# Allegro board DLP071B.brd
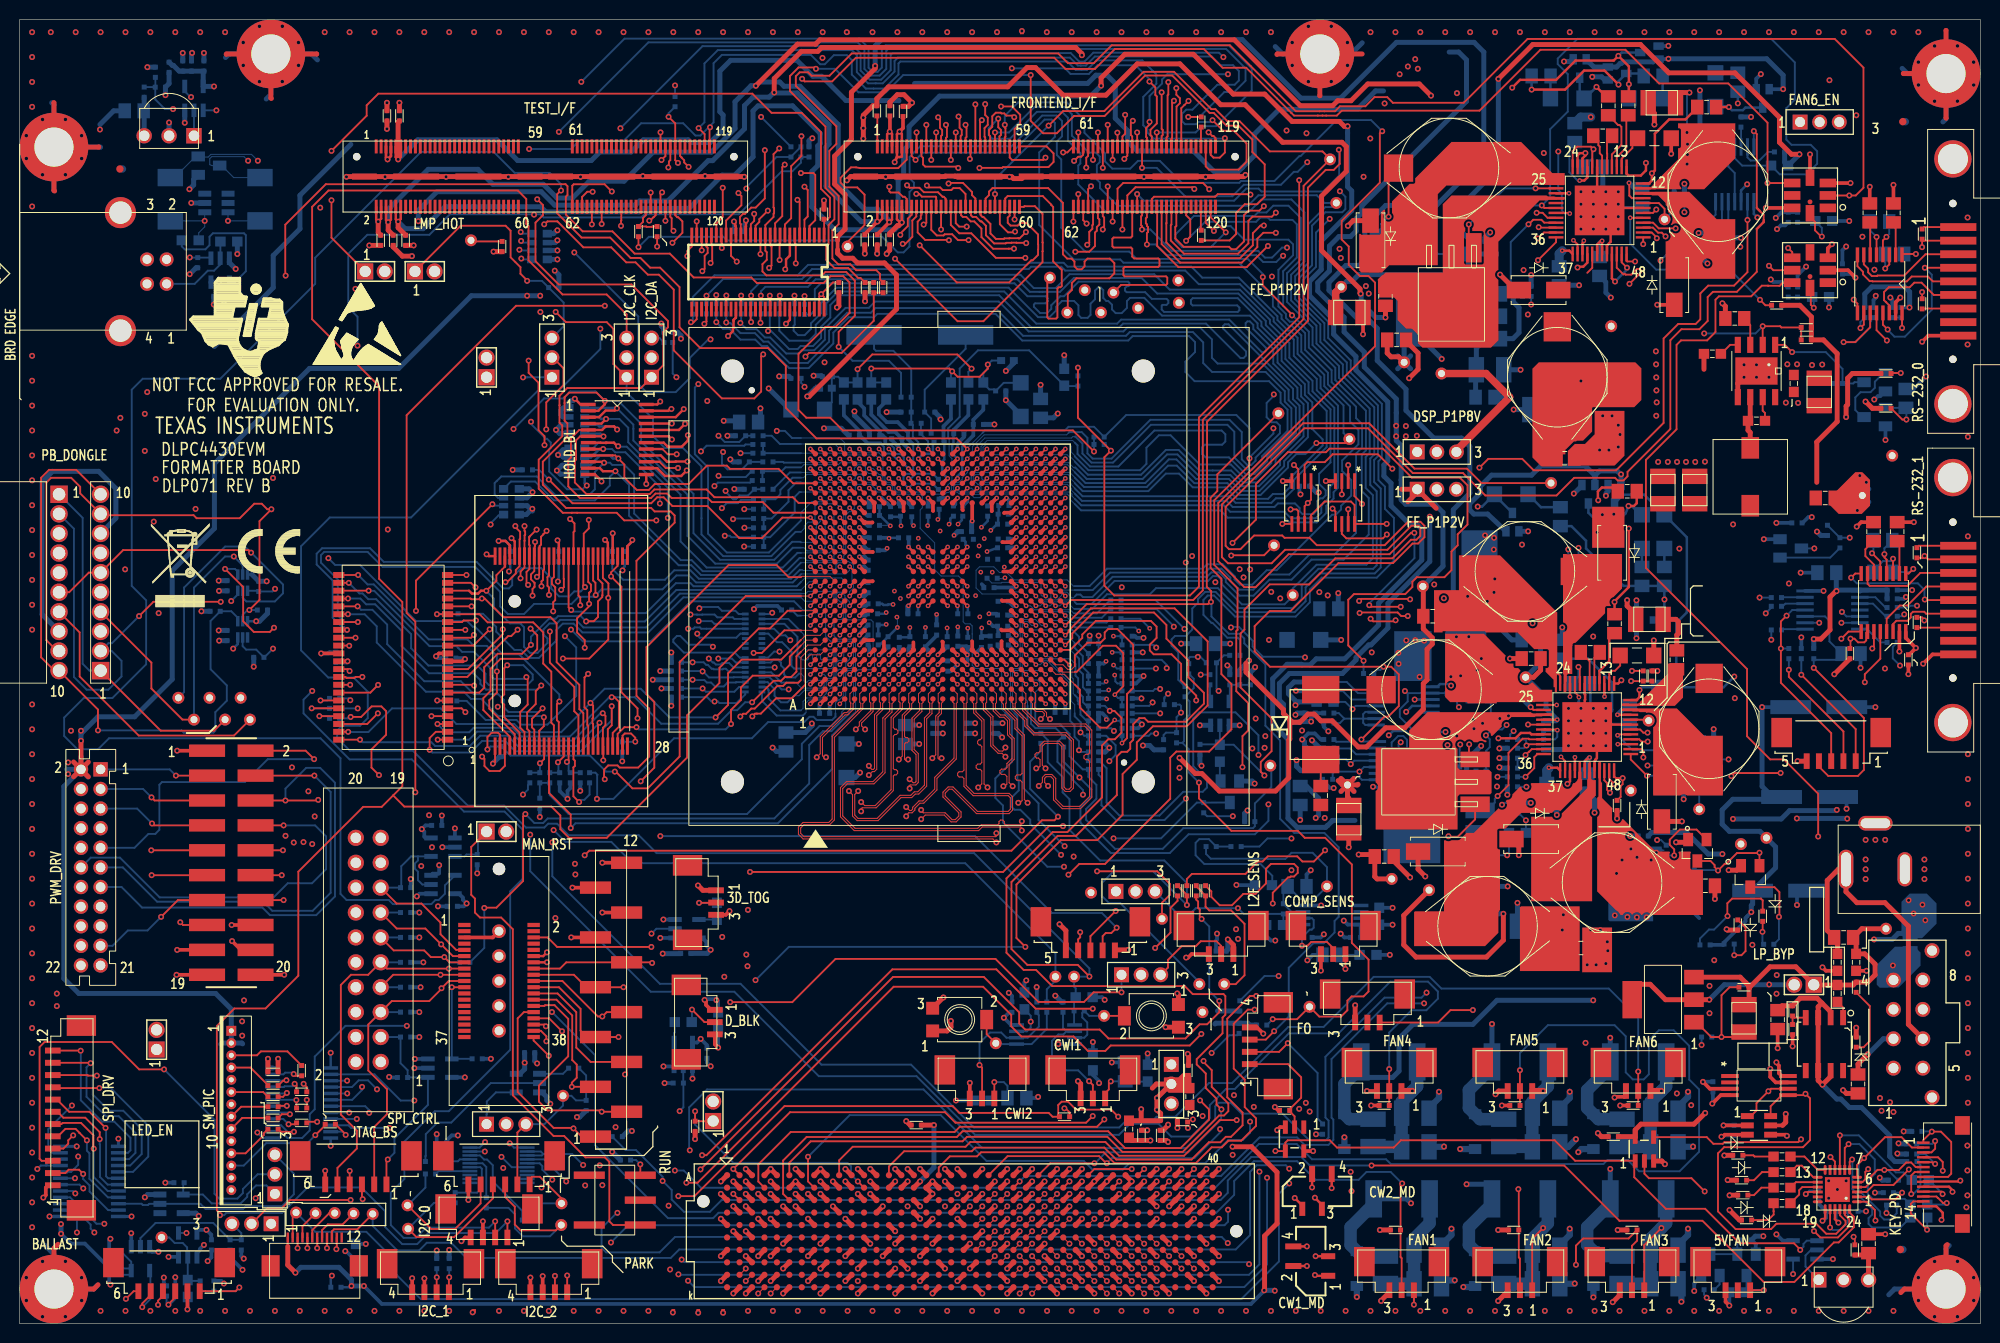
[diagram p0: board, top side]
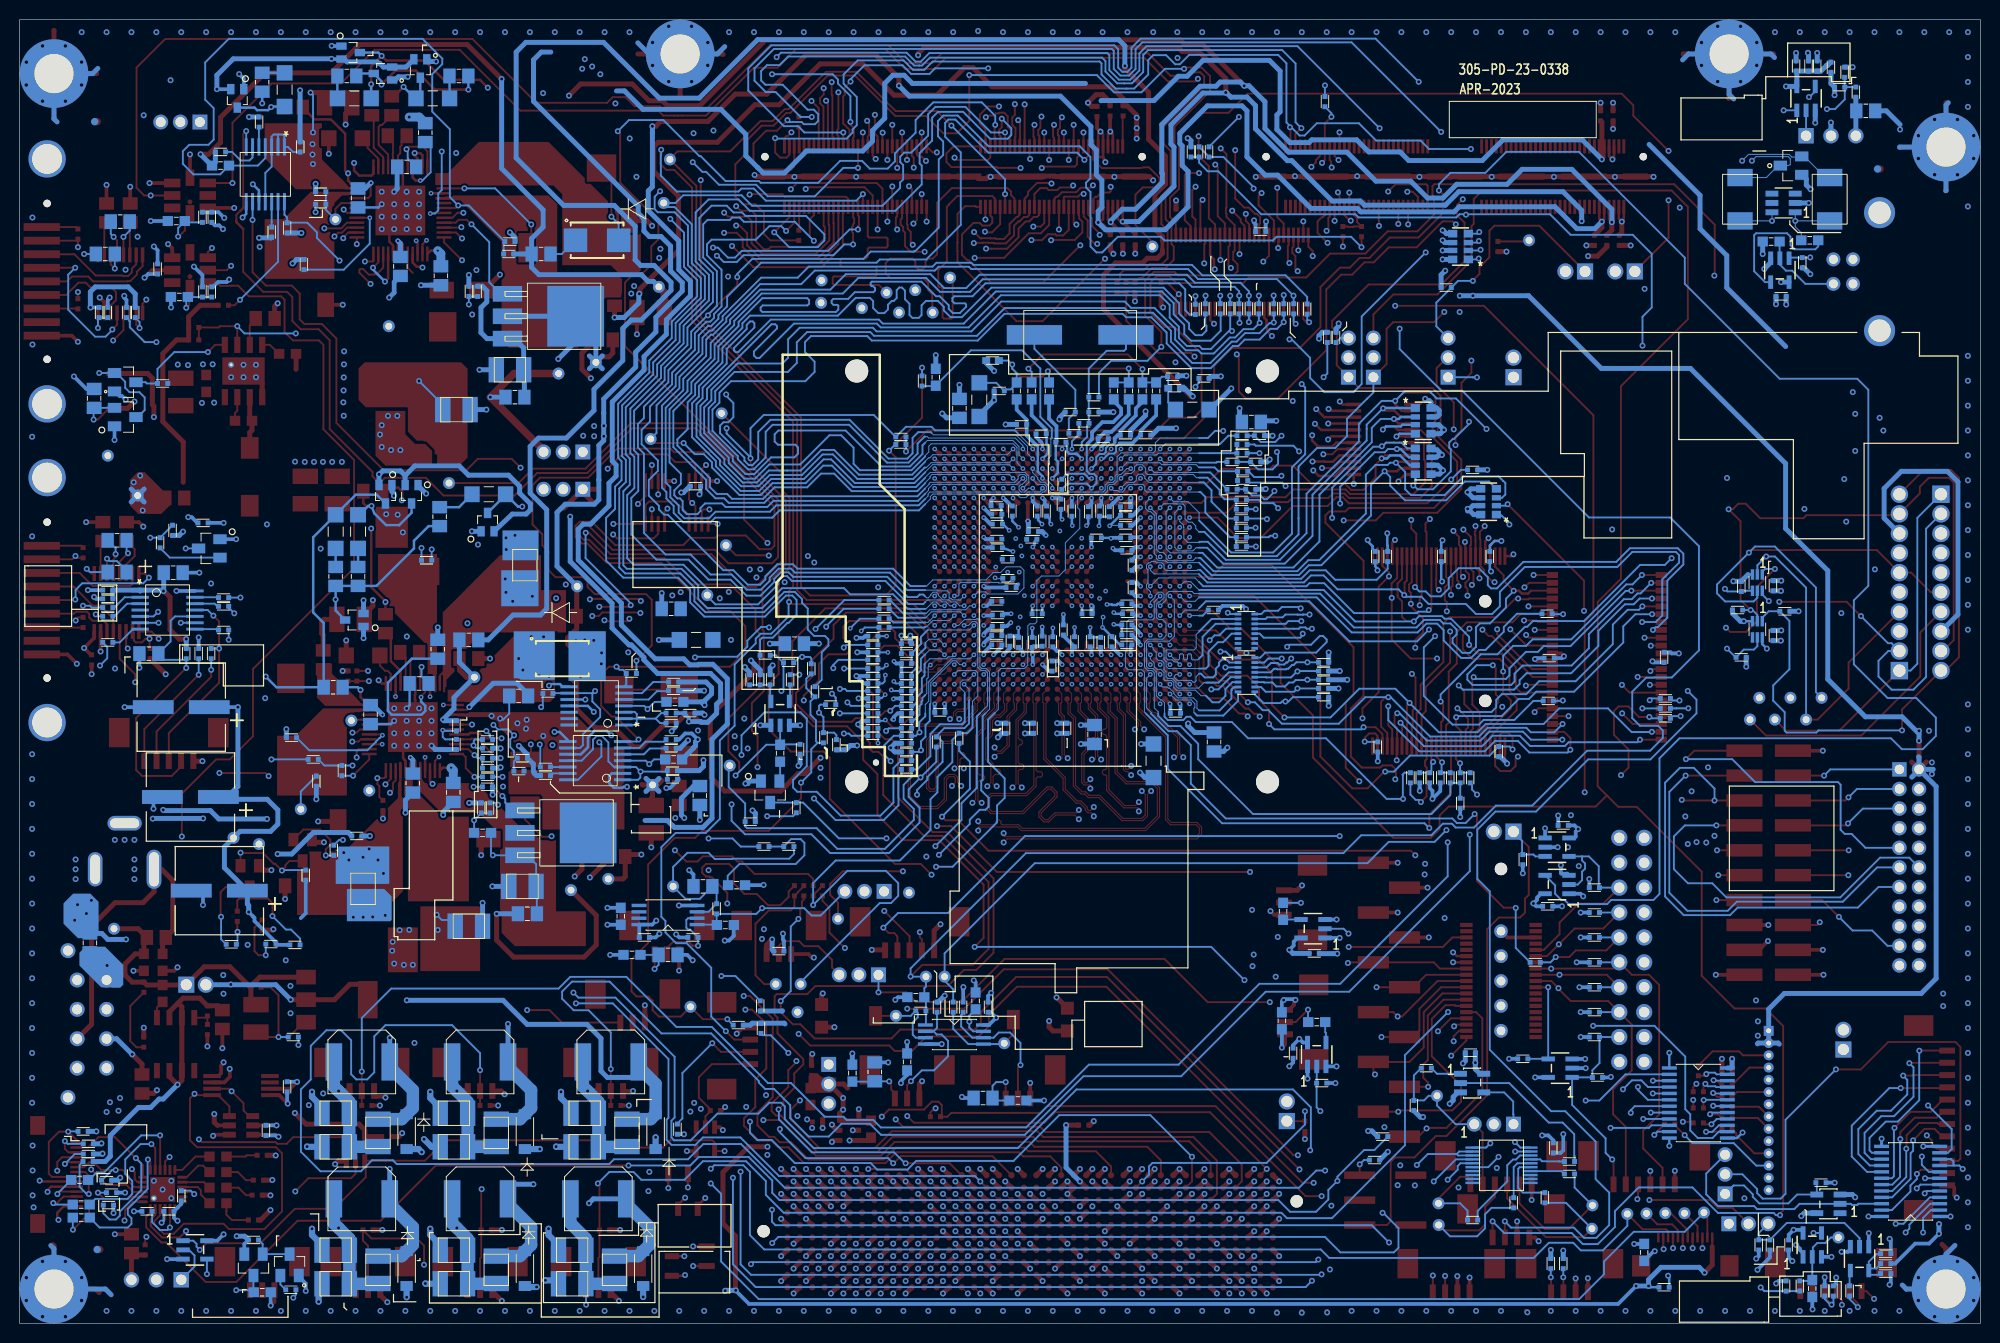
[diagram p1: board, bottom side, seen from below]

Outline 200 x 132.99 mm; copper layers: TOP, L02_GND1, L03_SIG1, L04_GND2, L05_SIG2, L06_GND3, L07_PWR, BOTTOM. Coordinates in mm from the lower left corner of the outline.
Outline path: 0,132.99 0,0 200,0 200,132.99 0,132.99

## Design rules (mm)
constraint set DEFAULT: min track width 0.193, pair gap 0.119
net group 10: nets CWCTR2 CWY1A CWY1B CWY1C CWY2A CWY2B CWY2C OUT1A_SNUB OUT1B OUT1B_SNUB OUT1C OUT1C_SNUB OUT2A OUT2A_SNUB OUT2B OUT2B_SNUB OUT2C OUT2C_SNUB
net group 20: nets FAN1_SW FAN2_SW FAN4_SW FAN5_SW FAN6_SW FAN6_SW_JUMP
net group 30: nets BT656_A_CLK P_CLK1 P_CLK2 P_CLK3 XTAL_IN XTAL_OUT
net group BT656: nets BT656_CLK BT656_D0 BT656_D1 BT656_D2 BT656_D3 BT656_D4 BT656_D5 BT656_D6 BT656_D7 BT656_D8 BT656_D9
net group BT656_A: nets BT656_A_D0 BT656_A_D1 BT656_A_D2 BT656_A_D3 BT656_A_D4 BT656_A_D5 BT656_A_D6 BT656_A_D7 BT656_A_D8 BT656_A_D9
net group BT656_B: nets BT656_B_CLK BT656_B_D0 BT656_B_D1 BT656_B_D3 BT656_B_D4 BT656_B_D5 BT656_B_D7 BT656_B_D8 BT656_B_D9
net group CLK: nets A_SSP0_CLK ADC_SCLK OCLKA_RES SP_WAVE_CLK SSP0_CLK_DMD SSP1_CLK SSP2_CLK TRACECLK
net group DIFF_SP: nets USB_DAT_N USB_DAT_NS USB_DAT_P USB_DAT_PS
net group GPIO: nets GPIO_40 GPIO_41 GPIO_42 GPIO_43 GPIO_44 GPIO_45 GPIO_46 GPIO_47 GPIO_48 GPIO_49 GPIO_50
net group P1_CLK BUS: nets AFE_CLK EXT_CLK P1_A0 P1_A1 P1_A2 P1_A3 P1_A4 P1_A5 P1_A6 P1_A7 P1_A8 P1_A9 P1_B0 P1_B1 P1_B2 P1_B3 P1_B4 P1_B5 P1_B6 P1_B7 P1_B8 P1_B9 P1_C0 P1_C1 P1_C2 P1_C3 P1_C4 P1_C5 P1_C6 P1_C7 P1_C8 P1_C9 P1_HSYNC P1_VSYNC P2_A0 P2_A1 P2_A2 P2_A3 P2_A4 P2_A5 P2_A6 P2_A7 P2_A8 P2_A9 P2_B0 P2_B1 P2_B2 P2_B3 P2_B4 P2_B5 P2_B6 P2_B7 P2_B8 P2_B9 P2_C0 P2_C1 P2_C2 P2_C3 P2_C4 P2_C5 P2_C6 P2_C7 P2_C8 P2_C9 P2_HSYNC P_DATAEN1 P_DATAEN2
net group PM_: nets PM_ADR_21 PM_ADR_22 PM_BLS0 PM_BLS0S PM_BLS1 PM_BLS1S PM_DAT_0 PM_DAT_1 PM_DAT_2 PM_DAT_3 PM_DAT_4 PM_DAT_5 PM_DAT_6 PM_DAT_7 PM_DAT_8 PM_DAT_9 PM_DAT_10 PM_DAT_11 PM_DAT_12 PM_DAT_13 PM_DAT_14 PM_DAT_15 PM_OESZ PM_OEZ PM_SRAM_CSSZ PM_SRAM_CSZ PM_WESZ PM_WEZ
net group PWR: nets A1P8V DMDSPARE0 FE_P1P2V LP_P3P3V MC_VCC P2P5V_CONN P3P3V_CONN P3P3V_LP P5V_CONN P5V_IR P5V_IR_CONN P12V_FIL P12V_IN SWNODE2_CORE
net group TRACEPKT_BGA: nets PIPESTAT0R PIPESTAT1R PIPESTAT2R TRACECLKR TRACEPKT0R TRACEPKT1R TRACEPKT2R TRACEPKT3R TRACEPKT4R TRACEPKT5R TRACEPKT6R TRACEPKT7R TRACESYNCR
net group TRACEPT_BUS: nets PIPESTAT0 PIPESTAT1 PIPESTAT2 TRACEPKT0 TRACEPKT1 TRACEPKT2 TRACEPKT3 TRACEPKT4 TRACEPKT5 TRACEPKT6 TRACEPKT7 TRACESYNC
net group U53: nets A1P8V_SENSE CWCTR1 FAN3_SW MTR_ARSTZ N16827292 N16830205 N16830576 N16830606 OCLKA OUT1A P_INTZ PGOOD PMD1K_CP1 PMD1K_FB_LIN1 PMD1K_FB_MOT1 PMD1K_FB_P3P3V PMD1K_FB_P5V PMD1K_GD_CORE PMD1K_GM_IN1 PMD1K_SENSE_MOT1 PMD1K_VCP PMD1K_VREG PMD_INTZ POSENSE PSENS PWRGOOD SSP0_CLK SWNODE_CORE SWNODE_MOT SWNODE_P3P3V SWNODE_P5V

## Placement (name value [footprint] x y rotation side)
ASY1  -  []  20.32 49.53 180 bottom
C1  22 uF  [CAP_1210]  167.51 124.52 0 top
C2  0.1 uF  [CAP_0402]  37.47 123.19 90 top
C3  0.1 uF  [CAP_0402]  38.73 123.19 90 top
C4  0.1 uF  [CAP_0402]  88.77 123.7 90 top
C5  0.1 uF  [CAP_0402]  90.11 123.63 90 top
C6  0.22 uF  [CAP_0805]  161.48 121.16 0 top
C7  0.1 uF  [CAP_0805]  188.72 113.28 90 top
C8  0.1 uF  [CAP_0805]  191.13 113.28 90 top
C9  0.1 uF  [CAP_0402]  36.83 110.49 270 top
C10  0.1 uF  [CAP_0402]  38.1 110.49 270 top
C11  0.1 uF  [CAP_0402]  39.37 110.49 270 top
C12  0.1 uF  [CAP_0402]  86.21 110.54 270 top
C13  0.1 uF  [CAP_0402]  87.48 110.54 270 top
C14  0.1 uF  [CAP_0402]  88.75 110.54 270 top
C15  47 uF  [CAP_1210]  135.64 103.12 180 top
C16  1 uF  [CAP_0805]  174.96 102.51 0 top
C17  22 pF  [CAP_0402]  182.25 101.6 0 top
C18  0.01 uF  [CAP_0603]  172.67 98.91 0 top
C19  0.1 uF  [CAP_0603]  180.97 95.89 90 top
C20  10 uF  [CAP_1210]  183.57 95.02 90 top
C21  0.1 uF  [CAP_0603]  177.16 92.08 0 top
C22  22 uF  [CAP_1210]  167.61 85.01 270 top
C23  22 uF  [CAP_1210]  170.87 85.01 270 top
C24  0.1 uF  [CAP_0805]  189.1 80.77 90 top
C25  0.1 uF  [CAP_0805]  191.52 80.77 90 top
C26  22 uF  [CAP_1210]  166.24 71.82 0 top
C27  4.7 uF  [CAP_0805]  154.18 67.82 0 top
C28  0.22 uF  [CAP_0805]  160.21 68.45 0 top
C29  0.1 uF  [CAP_0402]  166.5 66.04 270 top
C30  0.1 uF  [CAP_0402]  192.66 67.69 90 top
C31  47 uF  [CAP_1210]  135.57 51.44 90 top
C32  0.1 uF  [CAP_0603]  185.42 36.83 90 top
C33  0.1 uF  [CAP_0603]  187.32 36.83 90 top
C34  0.1 uF  [CAP_0402]  114.43 19.18 270 top
C35  0.1 uF  [CAP_0402]  116.33 19.18 90 top
C36  10 uF  [CAP_1210]  175.9 31.12 270 top
C37  1 uF  [CAP_0805]  179.32 30.99 90 top
C38  0.1 uF  [CAP_0402]  25.84 25.65 180 top
C39  0.1 uF  [CAP_0402]  119.21 25.81 270 top
C40  0.1 uF  [CAP_0402]  118.62 20.54 0 top
C41  0.1 uF  [CAP_0402]  162.56 19.05 0 top
C42  4.7 uF  [CAP_0805]  188.59 8.13 270 top
C500  0.001 uF  [CAP_0805]  175.26 126.62 90 bottom
C501  0.001 uF  [CAP_0805]  166.62 127.25 0 bottom
C502  0.001 uF  [CAP_0805]  155.19 127.25 0 bottom
C503  0.1 uF  [CAP_0402]  18.8 128.27 270 bottom
C504  0.1 uF  [CAP_0402]  16.64 128.27 270 bottom
C505  0.33 uF  [CAP_0805]  158.62 121.48 90 bottom
C506  4.7 uF  [CAP_0805]  11.68 123.7 0 bottom
C507  0.1 uF  [CAP_0805]  189.74 112.4 0 bottom
C508  0.1 uF  [CAP_0402]  181.36 112.84 270 bottom
C509  0.1 uF  [CAP_0402]  180.4 112.84 270 bottom
C510  180 pF  [CAP_0603]  179.51 118.11 0 bottom
C511  0.1 uF  [CAP_0402]  169.29 115.44 180 bottom
C512  0.33 uF  [CAP_0805]  165.48 114.81 90 bottom
C513  0.22 uF  [CAP_0805]  160.53 117.98 0 bottom
C514  0.1 uF  [CAP_0805]  191.26 109.09 0 bottom
C515  0.1 uF  [CAP_0402]  185.93 107.57 90 bottom
C516  0.1 uF  [CAP_0402]  181.36 105.22 270 bottom
C517  0.1 uF  [CAP_0402]  180.4 105.22 270 bottom
C518  0.33 uF  [CAP_0805]  161.16 107.82 90 bottom
C519  0.33 uF  [CAP_0805]  157.04 106.87 90 bottom
C520  0.1 uF  [CAP_0402]  73.41 111.38 0 bottom
C521  0.1 uF  [CAP_0402]  20.32 104.78 180 bottom
C522  47 uF  [CAP_1210]  149.99 97.28 180 bottom
C523  4.7 uF  [CAP_0805]  192.41 94.36 90 bottom
C524  47 uF  [CAP_1210]  155.45 93.22 0 bottom
C525  0.01 uF  [CAP_0603]  106.55 96.52 270 bottom
C526  10 uF  [CAP_0805]  104.14 93.34 90 bottom
C527  100 uF  [CAP_1206]  102.11 94.23 270 bottom
C528  0.1 uF  [CAP_0402]  100.08 95.12 0 bottom
C529  0.1 uF  [CAP_0402]  97.8 91.7 0 bottom
C530  0.1 uF  [CAP_0402]  95.8 90.75 0 bottom
C531  33 pF  [CAP_0402]  92.84 92.96 0 bottom
C532  33 pF  [CAP_0402]  90.42 92.96 180 bottom
C533  0.1 uF  [CAP_0402]  89.47 90.25 180 bottom
C534  0.1 uF  [CAP_0402]  87.21 90.6 180 bottom
C535  0.1 uF  [CAP_0402]  85.14 90.62 180 bottom
C536  0.1 uF  [CAP_0402]  82.4 96.57 180 bottom
C537  100 uF  [CAP_1206]  80.39 93.22 180 bottom
C538  10 uF  [CAP_0805]  74.36 91.95 180 bottom
C539  0.1 uF  [CAP_0402]  131.06 85.41 0 bottom
C540  0.1 uF  [CAP_0402]  100.39 83.44 180 bottom
C541  0.1 uF  [CAP_0402]  93.79 89.89 180 bottom
C542  0.1 uF  [CAP_0402]  93.79 83.57 270 bottom
C543  0.1 uF  [CAP_0402]  93.71 85.59 90 bottom
C544  0.1 uF  [CAP_0402]  87.19 83.31 0 bottom
C545  0.1 uF  [CAP_0805]  190.06 79.88 0 bottom
C546  0.1 uF  [CAP_0805]  190.06 76.64 0 bottom
C547  10 uF  [CAP_0805]  184.34 76.58 180 bottom
C548  0.1 uF  [CAP_0402]  181.29 81.66 180 bottom
C549  0.001 uF  [CAP_0805]  167.77 76.2 90 bottom
C550  0.001 uF  [CAP_0805]  165.48 76.2 90 bottom
C551  0.001 uF  [CAP_0805]  157.16 82.29 90 bottom
C552  22 uF  [CAP_1210]  148.46 77.34 270 bottom
C553  0.1 uF  [CAP_0402]  100.33 82.55 180 bottom
C554  0.1 uF  [CAP_0402]  100.33 80.01 180 bottom
C555  0.1 uF  [CAP_0402]  100.27 81.53 180 bottom
C556  0.1 uF  [CAP_0402]  100.27 79.12 180 bottom
C557  0.1 uF  [CAP_0402]  99.25 77.95 180 bottom
C558  0.1 uF  [CAP_0402]  98.74 82.87 270 bottom
C559  0.1 uF  [CAP_0402]  96.76 79.98 0 bottom
C560  0.1 uF  [CAP_0402]  96.58 80.77 180 bottom
C561  0.1 uF  [CAP_0402]  96.2 82.87 270 bottom
C562  0.1 uF  [CAP_0402]  95.25 82.87 270 bottom
C563  0.1 uF  [CAP_0402]  92.67 82.85 270 bottom
C564  0.1 uF  [CAP_0402]  91 82.8 270 bottom
C565  0.1 uF  [CAP_0402]  90.17 80.14 180 bottom
C566  0.1 uF  [CAP_0402]  89.85 82.87 270 bottom
C567  0.1 uF  [CAP_0402]  88.84 82.8 270 bottom
C568  0.1 uF  [CAP_0402]  87.19 82.42 0 bottom
C569  0.1 uF  [CAP_0402]  87.19 81.41 0 bottom
C570  0.1 uF  [CAP_0402]  87.19 80.14 0 bottom
C571  0.1 uF  [CAP_0402]  87.06 78.87 0 bottom
C572  0.1 uF  [CAP_0402]  86.55 77.34 90 bottom
C573  0.1 uF  [CAP_0402]  54.99 78.23 90 bottom
C574  0.1 uF  [CAP_0402]  191.01 74.8 180 bottom
C575  10 uF  [CAP_0805]  133.54 72.9 0 bottom
C576  100 uF  [CAP_1206]  131 69.72 0 bottom
C577  10 uF  [CAP_0805]  120.97 69.34 0 bottom
C578  15 pF  [CAP_0402]  112.97 70.1 0 bottom
C579  0.1 uF  [CAP_0402]  100.33 73.66 180 bottom
C580  0.1 uF  [CAP_0402]  100.33 70.17 180 bottom
C581  0.1 uF  [CAP_0402]  100.33 69.22 0 bottom
C582  0.1 uF  [CAP_0402]  100.27 72.26 180 bottom
C583  0.1 uF  [CAP_0402]  100.27 71.12 180 bottom
C584  0.1 uF  [CAP_0402]  99 69.6 90 bottom
C585  0.1 uF  [CAP_0402]  98.87 75.06 180 bottom
C586  0.1 uF  [CAP_0402]  98.11 69.47 90 bottom
C587  0.1 uF  [CAP_0402]  96.71 69.47 90 bottom
C588  0.1 uF  [CAP_0402]  96.2 72.39 180 bottom
C589  0.1 uF  [CAP_0402]  95.69 69.6 90 bottom
C590  0.1 uF  [CAP_0402]  94.61 69.53 90 bottom
C591  0.1 uF  [CAP_0402]  93.54 70.74 90 bottom
C592  0.1 uF  [CAP_0402]  92.39 69.53 90 bottom
C593  0.1 uF  [CAP_0402]  91.12 72.39 0 bottom
C594  0.1 uF  [CAP_0402]  90.81 69.53 90 bottom
C595  0.1 uF  [CAP_0402]  89.73 69.47 90 bottom
C596  0.1 uF  [CAP_0402]  88.58 69.53 90 bottom
C597  0.1 uF  [CAP_0402]  87.06 73.41 0 bottom
C598  0.1 uF  [CAP_0402]  87.06 71.25 0 bottom
C599  0.1 uF  [CAP_0402]  87.06 70.23 0 bottom
C600  0.1 uF  [CAP_0402]  87.06 69.22 0 bottom
C601  0.1 uF  [CAP_0402]  87 72.39 0 bottom
C602  0.1 uF  [CAP_0402]  86.55 75.06 270 bottom
C603  0.1 uF  [CAP_0402]  21.16 75.25 270 bottom
C604  0.1 uF  [CAP_0402]  21.16 70.17 270 bottom
C605  0.001 uF  [CAP_0805]  186.82 68.33 180 bottom
C606  100 uF  [CAP-FK-V-CASEE_PAN]  183.51 62.87 90 bottom
C607  0.33 uF  [CAP_0805]  164.21 62.1 90 bottom
C608  0.22 uF  [CAP_0805]  159.26 65.28 0 bottom
C609  0.33 uF  [CAP_0805]  157.35 68.77 90 bottom
C610  68 pF  [CAP_0603]  133.16 63.4 180 bottom
C611  0.1 uF  [CAP_0402]  131.64 62.26 0 bottom
C612  0.1 uF  [CAP_0402]  125.54 65.66 270 bottom
C613  15 pF  [CAP_0402]  112.97 68.45 0 bottom
C614  15 pF  [CAP_0402]  112.97 66.04 0 bottom
C615  15 pF  [CAP_0402]  112.97 65.28 0 bottom
C616  15 pF  [CAP_0402]  112.97 63.75 0 bottom
C617  15 pF  [CAP_0402]  112.97 61.47 0 bottom
C618  15 pF  [CAP_0402]  112.97 60.71 0 bottom
C619  15 pF  [CAP_0402]  109.54 66.04 0 bottom
C620  15 pF  [CAP_0402]  109.54 63.75 0 bottom
C621  15 pF  [CAP_0402]  109.54 62.23 0 bottom
C622  15 pF  [CAP_0402]  109.54 61.47 0 bottom
C623  0.1 uF  [CAP_0402]  106.13 62.33 0 bottom
C624  0.1 uF  [CAP_0402]  99.38 60.71 270 bottom
C625  0.1 uF  [CAP_0402]  96.58 60.71 270 bottom
C626  0.1 uF  [CAP_0402]  94.68 67.06 270 bottom
C627  0.1 uF  [CAP_0402]  93.15 60.71 270 bottom
C628  0.1 uF  [CAP_0402]  82.11 62.23 180 bottom
C629  0.1 uF  [CAP_0402]  43.98 67.87 0 bottom
C630  0.1 uF  [CAP_0402]  32.26 67.95 90 bottom
C631  100 uF  [CAP-FK-V-CASEE_PAN]  182.58 53.7 90 bottom
C632  0.33 uF  [CAP_0805]  159.89 55.12 90 bottom
C633  0.33 uF  [CAP_0805]  155.77 54.17 90 bottom
C634  180 pF  [CAP_0603]  133.29 57.53 180 bottom
C635  10 uF  [CAP_0805]  130.62 53.85 270 bottom
C636  10 uF  [CAP_0805]  90.36 60.07 270 bottom
C637  100 uF  [CAP_1206]  84.34 57.39 270 bottom
C638  10 uF  [CAP_0805]  78.17 59.31 270 bottom
C639  100 uF  [CAP-FK-V-CASEE_PAN]  179.63 44.14 90 bottom
C640  0.1 uF  [CAP_0402]  165.61 49.72 0 bottom
C641  22 uF  [CAP_1210]  164.97 44.32 90 bottom
C642  68 pF  [CAP_0603]  152.78 50.04 180 bottom
C643  47 uF  [CAP_1210]  148.72 44.58 180 bottom
C644  1 uF  [CAP_0805]  130.3 44.58 180 bottom
C645  0.01 uF  [CAP_0603]  126.87 44.7 0 bottom
C646  0.1 uF  [CAP_0402]  42.55 50.8 180 bottom
C647  47 uF  [CAP_1210]  154.18 40.51 0 bottom
C648  0.1 uF  [CAP_0603]  138.68 41.53 270 bottom
C649  0.1 uF  [CAP_0603]  137.54 37.59 180 bottom
C650  0.1 uF  [CAP_0402]  136.27 39.37 0 bottom
C651  0.1 uF  [CAP_0402]  122.56 37.97 0 bottom
C652  0.1 uF  [CAP_0402]  44.13 42.55 0 bottom
C653  0.1 uF  [CAP_0402]  172.72 24.13 90 bottom
C654  0.1 uF  [CAP_0402]  52.02 27.61 0 bottom
C655  0.1 uF  [CAP_0402]  174.88 19.69 270 bottom
C656  22 uF  [CAP_1210]  167.77 18.01 180 bottom
C657  22 uF  [CAP_1210]  155.7 18.01 180 bottom
C658  22 uF  [CAP_1210]  142.37 18.01 180 bottom
C659  0.1 uF  [CAP_0402]  43.56 17.91 90 bottom
C660  0.1 uF  [CAP_0402]  184.78 11.43 0 bottom
C661  0.1 uF  [CAP_0603]  109.47 26.67 90 bottom
C662  0.1 uF  [CAP_0402]  101.22 32.26 270 bottom
C663  0.1 uF  [CAP_0603]  34.29 7.24 270 bottom
C664  0.1 uF  [CAP_0402]  67.94 37.74 0 bottom
C665  0.1 uF  [CAP_0402]  19.56 8 90 bottom
C666  0.1 uF  [CAP_0603]  175.26 3.18 0 bottom
C667  22 uF  [CAP_1210]  167.77 4.04 180 bottom
C668  22 uF  [CAP_1210]  155.7 4.04 180 bottom
C669  22 uF  [CAP_1210]  143.64 4.04 180 bottom
C670  0.1 uF  [CAP_0603]  115.06 25.53 270 bottom
C671  0.1 uF  [CAP_0603]  98.17 22.73 0 bottom
C672  0.1 uF  [CAP_0402]  32.26 3.68 0 bottom
C673  0.1 uF  [CAP_0603]  71.25 30.86 90 bottom
C674  0.1 uF  [CAP_0402]  70.1 27.56 90 bottom
C675  0.1 nF  [CAP_0603]  17.14 3.56 90 bottom
C676  0.1 uF  [CAP_0402]  9.65 5.08 0 bottom
D1  B220A  [DIO-SMA]  137.79 110.49 90 top
D2  B220A  [DIO-SMA]  154.94 105.41 180 top
D3  B220A  [DIO-SMA]  168.78 105.92 270 top
D4  B220A  [DIO-SMA]  162.43 78.61 90 top
D5  MUR320T3G  [SMC_ST]  132.72 61.09 90 top
D6  B220A  [DIO-SMA]  167.51 53.21 270 top
D7  B220A  [DIO-SMA]  144.65 48.13 180 top
D8  B220A  [DIO-SMA]  154.18 49.4 180 top
D9  LED_GRN  [LED-0402-REV]  175.26 40.64 90 top
D10  LED_GRN  [LED-0402-REV]  187.34 28.69 270 top
D11  RED LED  [LED-0402-REV]  177.8 41.53 90 top
D12  LED_GRN  [LED-0402-REV]  176.15 10.54 180 top
D13  RED LED  [LED-0402-REV]  175.77 13.08 180 top
D14  LED_GRN  [LED-0402-REV]  175.64 14.61 180 top
D15  RED LED  [LED-0402-REV]  175.26 17.15 180 top
D500  MURS220T3G  [DIO-SMB]  141.1 110.49 180 bottom
D501  B340B  [DIO-SMB]  144.65 67.82 180 bottom
D502  STPS0560Z  [SOD-123]  160.53 19.56 270 bottom
D503  STPS0560Z  [SOD-123]  148.46 19.56 270 bottom
D504  STPS0560Z  [SOD-123]  135.13 19.56 270 bottom
D505  STPS0560Z  [SOD-123]  160.53 5.59 270 bottom
D506  STPS0560Z  [SOD-123]  148.46 5.59 270 bottom
D507  STPS0560Z  [SOD-123]  136.4 5.59 270 bottom
DN500  BAT54SWT1G  [SOT_323]  177.8 124.97 180 bottom
DN501  BAT54SWT1G  [SOT_323]  166.24 129.64 90 bottom
DN502  BAT54SWT1G  [SOT_323]  162.94 127.51 270 bottom
DN503  BAT54SWT1G  [SOT_323]  159.13 128.02 180 bottom
DN504  BAT54C  [SOT23AVXC]  19.31 118.11 270 bottom
DN505  BAT54SWT1G  [SOT_323]  162.69 84.58 180 bottom
DN506  BAT54SWT1G  [SOT_323]  160.02 84.58 180 bottom
DN507  BAT54SWT1G  [SOT_323]  152.27 81.74 0 bottom
DN508  BAT54SWT1G  [SOT_323]  165.86 71.75 270 bottom
FB1  80 ohm  [IND_0805]  186.06 39.37 0 top
FB2  100 Ohm  [FLTR_0603]  113.16 19.81 270 top
FB3  100 Ohm  [FLTR_0603]  119.34 23.13 270 top
FB500  470 Ohm  [FLTR_0603]  98.3 95.12 270 bottom
FB501  470 Ohm  [FLTR_0603]  96.77 95.12 270 bottom
FB502  470 Ohm  [FLTR_0603]  95 95.12 270 bottom
FB503  470 Ohm  [FLTR_0603]  88.39 95.12 270 bottom
FB504  470 Ohm  [FLTR_0603]  86.87 95.12 270 bottom
FB505  470 Ohm  [FLTR_0603]  85.47 95.12 270 bottom
FB506  470 Ohm  [FLTR_0603]  84.07 95.12 270 bottom
J1  conn_120_QTH  [CN120_QTH_SAMTEC]  53.62 116.99 0 top
J2  conn_120_QTH  [CN120_QTH_SAMTEC]  104.74 116.99 0 top
J3  JUMPER-1x3  [HDR1X3-TMM1030X-X-S_SAM]  183.61 122.56 0 top
J4  CON4  [CONN4-67068-1000-A_MOLEX]  0 107.32 270 top
J5  HDR_2  [HDR2_2MM]  35.24 107.31 0 top
J6  HDR_2  [HDR2_2MM]  40.32 107.31 0 top
J7  RS232  [KYCON-CN9SMTA]  196.42 106.3 270 top
J8  HDR_2  [HDR2_2MM]  47.62 96.52 90 top
J9  JUMPER-1x3  [HDR1X3-TMM1030X-X-S_SAM]  54.29 98.52 90 top
J10  JUMPER-1x3  [HDR1X3-TMM1030X-X-S_SAM]  61.91 98.52 90 top
J11  JUMPER-1x3  [HDR1X3-TMM1030X-X-S_SAM]  64.45 98.52 90 top
J12  JUMPER-1x3  [HDR1X3-TMM1030X-X-S_SAM]  144.56 88.9 0 top
J13  JUMPER-1x3  [HDR1X3-TMM1030X-X-S_SAM]  144.56 85.09 0 top
J14  CONN10RA  [CONN10-SQT-RA-REV_SAM]  4.02 84.58 0 top
J15  CONN10  [CONN10-SQT_SAM]  8.26 66.59 180 top
J16  RS232  [KYCON-CN9SMTA]  196.42 73.79 270 top
J17  CON5  [CONN5-53398-0590-A_MOLEX]  184.78 58.42 180 top
J18  CON22  [CONN22-B22B-PHD_JST]  8.26 56.52 180 top
J19  CON20A  [CONN20-TSM-110-0X-X-DV-A_SAMTEC]  21.59 46.99 270 top
J20  HDR_2  [HDR2_2MM]  47.62 50.17 0 top
J21  JUMPER-1x3  [HDR1X3-TMM1030X-X-S_SAM]  113.82 44.07 0 top
J22  POWER_12V_INPUT  [JACK3-DCPOWER_CUI_MOD]  186.3 46.32 0 top
J23  CON20A  [HDR10X2-5103308_TYCO]  36.83 26.67 180 top
J24  CON5  [CONN5-53398-0590-A_MOLEX]  109.22 39.12 180 top
J25  CON3  [CN3_53398_MOLEX]  122.56 38.73 180 top
J26  CON3  [CN3_53398_MOLEX]  133.98 38.73 180 top
J27  ARM_TRACE_PORT  [MICTOR_HPA]  48.89 34.93 90 top
J28  CON12  [CONN12-SMT-TSM-112-SV_SAMTEC]  60.33 33.02 0 top
J29  JUMPER-1x3  [HDR1X3-TMM1030X-X-S_SAM]  114.39 35.56 0 top
J30  CON3  [CN3_53398_MOLEX]  137.48 31.75 180 top
J31  HDR_2  [HDR2_2MM]  183.01 34.54 180 top
J32  JUMPER_8A  [CONN8-43045-0813_MOLEX]  191.13 26.04 270 top
J33  CON12  [CONN12-53398_MOLEX]  4.45 20.96 90 top
J34  HDR_2  [HDR2_2MM]  13.97 27.94 90 top
J35  CON14  [CONN14-53047_MLX]  21.59 29.85 90 top
J36  CONN_4  [CONN4-53398-A_MOLEX]  125.48 28.32 90 top
J37  CON3  [CN3_53398_MOLEX]  139.7 24.77 180 top
J38  CON3  [CN3_53398_MOLEX]  153.03 24.77 180 top
J39  CON3  [CN3_53398_MOLEX]  165.1 24.77 180 top
J40  JUMPER-1x3  [HDR1X3-TMM1030X-X-S_SAM]  23.65 10.16 180 top
J41  JUMPER-1x3  [HDR1X3-TMM1030X-X-S_SAM]  26.03 15.21 90 top
J42  CON6  [CONN6-53398-0690-A_MOLEX]  34.29 15.24 180 top
J43  CON6  [CONN6-53398-0690-A_MOLEX]  48.89 15.24 180 top
J44  JUMPER-1x3  [HDR1X3-TMM1030X-X-S_SAM]  49.62 20.32 0 top
J45  HDR_2  [HDR2_2MM]  70.74 20.64 90 top
J46  JUMPER-1x3  [HDR1X3-TMM1030X-X-S_SAM]  117.47 24.42 270 top
J47  CON14  [CONN14-XF2M-A_OMRON]  194.18 15.19 90 top
J48  CON6  [CONN6-53398-0690-A_MOLEX]  15.24 4.34 180 top
J49  CONN_4  [CONN4-53398-A_MOLEX]  47.88 8.76 180 top
J50  CONN_4  [CONN4-53398-A_MOLEX]  41.91 3.18 180 top
J51  CONN_4  [CONN4-53398-A_MOLEX]  53.98 3.18 180 top
J52  CON3  [CN3_53398_MOLEX]  69.85 30.73 270 top
J53  CON3  [CN3_53398_MOLEX]  69.98 42.93 270 top
J54  12 HEADER  [CONN12-FH12_HRS]  30.1 8.76 0 top
J55  CON3  [CN3_53398_MOLEX]  98.17 24 180 top
J56  CON4  [CONN4-52808_MOLEX]  132.33 13.46 0 top
J57  CON3  [CN3_53398_MOLEX]  109.47 24 180 top
J58  CON4  [CONN4-52808_MOLEX]  131.7 6.35 90 top
J59  CON3  [CN3_53398_MOLEX]  140.97 4.45 180 top
J60  CON3  [CN3_53398_MOLEX]  153.03 4.45 180 top
J61  CON3  [CN3_53398_MOLEX]  164.47 4.45 180 top
J62  CON3  [CN3_53398_MOLEX]  175.26 4.45 180 top
J63  FMC 400POS CONN FEMALE  [CONN400-ASP-134486-01_SAM_MOD]  96.93 9.4 180 top
L1  4.7 uH  [IND_SRR1005]  145.8 117.86 0 top
L2  33 uH  [IND_SRR1005]  173.23 115.44 90 top
L3  10 uH  [IND_SRR1005]  156.84 96.52 90 top
L4  2.2 uH  [IND2-7447789002-7332_WURTH]  176.53 86.36 180 top
L5  15 uH  [IND_SRR1005]  153.54 76.71 180 top
L6  4.7 uH  [IND_SRR1005]  144.02 64.64 0 top
L7  33 uH  [IND_SRR1005]  172.34 60.66 90 top
L8  10 uH  [IND_SRR1005]  162.43 44.96 180 top
L9  10 uH  [IND_SRR1005]  149.73 40.51 180 top
L500  47 uH  [IND_SERH]  165.1 26.67 180 bottom
L501  47 uH  [IND_SERH]  153.03 26.67 180 bottom
L502  47 uH  [IND_SERH]  139.7 26.67 180 bottom
L503  47 uH  [IND_SERH]  165.1 12.7 180 bottom
L504  47 uH  [IND_SERH]  153.03 12.7 180 bottom
L505  47 uH  [IND_SERH]  140.97 12.7 180 bottom
MT1  MOUNTING HOLE  [MH276-157GND-A]  25.63 129.5 22.5 top
MT2  MOUNTING HOLE  [MH276-157GND-A]  132.63 129.5 22.5 top
MT3  MOUNTING HOLE  [MH276-157GND-A]  196.5 127.5 22.5 top
MT4  MOUNTING HOLE  [MH276-157GND-A]  3.5 120 22.5 top
MT5  MOUNTING HOLE  [MH276-157GND-A]  3.5 3.5 292.5 top
MT6  MOUNTING HOLE  [MH276-157GND-A]  196.5 3.5 22.5 top
NOREF  -  []  0 0 0 top
NOREF#2  -  []  34.72 101.42 0 top
NOREF#3  -  []  0 132.99 0 top
NOREF#4  -  []  3.5 3.5 0 top
NOREF#5  -  [unnamed#2]  93.66 76.2 270 top
NOREF#6  -  []  3.5 3.5 0 top
NOREF#7  -  []  39.57 160.21 0 top
NOREF#8  -  []  200 132.99 0 top
NOREF#9  -  [unnamed#3]  10.23 117.77 0 top
NOREF#10  -  [unnamed#3]  191.84 7.53 0 top
NOREF#11  -  []  0 0 0 top
NOREF#12  -  []  255.8 67.67 0 top
NOREF#13  -  [unnamed#3]  192.09 122.59 0 top
NOREF#14  -  []  140.97 116.33 180 bottom
NOREF#15  -  [unnamed#3]  192.09 7.53 180 bottom
NOREF#16  -  [unnamed#3]  192.35 122.59 180 bottom
NOREF#17  -  [unnamed#3]  10.48 117.77 180 bottom
NOREF#18  -  []  148.08 71.88 180 bottom
Q1  NTD14N03RT4G  [SM_TO_252_DPAK]  146.05 105.41 180 top
Q2  NTD14N03RT4G  [SM_TO_252_DPAK]  144.15 55.25 90 top
Q3  2N2222A  [SOT23AVXD]  171.13 48.26 0 top
Q4  MMBT6427  [SOT23AVXD]  176.53 45.59 0 top
Q5  NDT456P  [SOT223]  167.64 33.02 90 top
Q500  NTD14N03RT4G  [SM_TO_252_DPAK]  145.92 102.74 270 bottom
Q501  2N2222A  [SOT23AVXD]  189.23 96.01 90 bottom
Q502  2N2222A  [SOT23AVXD]  189.23 92.46 90 bottom
Q503  2N2222A  [SOT23AVXD]  180.66 79.06 270 bottom
Q504  2N2222A  [SOT23AVXD]  123.44 54.23 180 bottom
Q505  NTD14N03RT4G  [SM_TO_252_DPAK]  144.65 50.04 270 bottom
Q506  FDN306P  [SOT23-3_FC]  176.15 5.97 180 bottom
Q507  2N2222A  [SOT23AVXD]  172.47 5.97 0 bottom
R1  1K  [RES_0402]  82.04 113.16 270 top
R2  0  [RES_0402]  87.44 123.7 270 top
R3  0  [RES_0402]  120.52 122.56 270 top
R4  0  [RES_0805]  162.05 124.21 90 top
R5  0  [RES_0805]  164.08 124.21 90 top
R6  2.2  [RES_1206]  166.75 120.9 0 top
R7  0  [RES_0805]  172.09 124.08 0 top
R8  3.3K  [RES_0402]  49.21 109.86 90 top
R9  0  [RES_0402]  63.12 111.38 90 top
R10  0  [RES_0402]  65.02 111.38 90 top
R11  1K  [RES_0402]  83.57 105.66 90 top
R12  1K  [RES_0402]  86.23 105.66 90 top
R13  0  [RES_0402]  87.12 105.66 90 top
R14  0  [RES_0402]  88.07 105.66 90 top
R15  0  [RES_0402]  120.52 111 90 top
R16  0.1  [RES_0805]  139.32 104.78 270 top
R17  169K  [RES_0402]  179.22 103.86 180 top
R18  0  [RES_0402]  194.06 111.12 270 top
R19  0  [RES_0402]  194.06 104.01 90 top
R20  0.01  [RES_0805]  140.46 100.33 0 top
R21  110K  [RES_0402]  182.25 100.33 180 top
R22  10K  [RES_0402]  190.37 96.9 180 top
R23  10K  [RES_0402]  190.37 93.34 180 top
R24  0.01  [RES_0805]  157.61 88.27 0 top
R25  0  [RES_0805]  163.98 84.89 0 top
R26  0.01  [RES_0805]  184.18 84.2 0 top
R27  0.01  [RES_0805]  144.15 72.14 0 top
R28  0  [RES_0805]  162.69 71.37 90 top
R29  0  [RES_0402]  193.53 78.61 270 top
R30  0  [RES_0402]  193.53 71.5 90 top
R31  2.2  [RES_1206]  164.97 68.14 0 top
R32  10K  [RES_0402]  165.61 66.04 270 top
R33  0.01  [RES_0805]  169.04 67.69 270 top
R34  10K  [RES_0402]  186.69 68.33 270 top
R35  0.01  [RES_0805]  132.72 53.85 270 top
R36  3.3K  [RES_0402]  162.94 52.83 90 top
R37  33  [RES_0402]  118.11 44.13 90 top
R38  33  [RES_0402]  119.06 44.13 270 top
R39  33  [RES_0402]  120.02 44.13 90 top
R40  33  [RES_0402]  120.97 44.13 270 top
R41  0.01  [RES_0805]  139.19 47.62 0 top
R42  0.01  [RES_0805]  171.96 44.64 0 top
R43  0.01  [RES_0805]  159.26 38.29 0 top
R44  1K  [RES_0402]  91.46 20.22 180 top
R45  2K  [RES_0402]  175.9 34.29 0 top
R46  470  [RES_0402]  180.85 31.88 270 top
R47  1  [RES_0603]  185.42 33.66 270 top
R48  3.3K  [RES_0402]  187.32 34.29 270 top
R49  33  [RES_0402]  25.84 24.26 180 top
R50  33  [RES_0402]  25.84 23.11 180 top
R51  33  [RES_0402]  25.84 22.1 180 top
R52  33  [RES_0402]  25.84 20.96 180 top
R53  33  [RES_0402]  28.77 25.78 90 top
R54  33  [RES_0402]  28.77 23.62 0 top
R55  33  [RES_0402]  28.77 21.97 0 top
R56  1K  [RES_0402]  129.03 21.72 0 top
R57  3.3K  [RES_0402]  139.19 22.23 180 top
R58  3.3K  [RES_0402]  152.53 22.23 180 top
R59  3.3K  [RES_0402]  164.59 22.23 180 top
R60  768  [RES_0402]  180.85 29.97 270 top
R61  0.01  [RES_0805]  187.52 24.42 90 top
R62  33  [RES_0402]  25.84 19.81 180 top
R63  33  [RES_0402]  28.77 20.45 0 top
R64  33  [RES_0402]  31.69 20.32 180 top
R65  33  [RES_0402]  106.58 21.08 180 top
R66  33  [RES_0402]  68.9 20.1 90 top
R67  220  [RES_0603]  179.77 17.02 180 top
R68  220  [RES_0603]  179.77 15.43 180 top
R69  220  [RES_0603]  179.77 13.84 180 top
R70  220  [RES_0603]  179.77 12.26 180 top
R71  3.3K  [RES_0402]  140.34 9.53 180 top
R72  3.3K  [RES_0402]  152.4 9.53 180 top
R73  3.3K  [RES_0402]  164.47 9.53 180 top
R74  33  [RES_0402]  187.2 7.49 90 top
R500  150  [RES_1206]  172.97 125.86 270 bottom
R501  150  [RES_1206]  165.86 124.97 180 bottom
R502  150  [RES_1206]  157.86 124.97 0 bottom
R503  0  [RES_0402]  66.85 124.64 90 bottom
R504  0  [RES_0402]  17.53 128.27 90 bottom
R505  0  [RES_0402]  15.24 128.14 270 bottom
R506  0  [RES_0402]  14.35 126.11 0 bottom
R507  0  [RES_0402]  13.84 127.63 90 bottom
R508  33  [RES_0402]  12.7 125.6 90 bottom
R509  909  [RES_0402]  179.51 119.51 0 bottom
R510  5.1K  [RES_0402]  175.58 122.56 270 bottom
R511  0  [RES_0402]  171.39 120.02 90 bottom
R512  1K  [RES_0402]  80.52 119.51 270 bottom
R513  0  [RES_0402]  79.69 119.51 270 bottom
R514  0  [RES_0402]  78.68 119.51 90 bottom
R515  10  [RES_0603]  184.02 112.46 0 bottom
R516  24.9K  [RES_0402]  172.72 111.76 270 bottom
R517  10K  [RES_0402]  169.29 114.17 180 bottom
R518  22  [RES_2010]  24.51 114.68 90 bottom
R519  22  [RES_2010]  15.37 114.68 90 bottom
R520  10  [RES_0603]  183.71 104.71 180 bottom
R521  80.6K  [RES_0402]  174.29 111.33 270 bottom
R522  3.3K  [RES_0402]  171.01 108.01 270 bottom
R523  1.6K  [RES_0402]  154.18 105.28 270 bottom
R524  2K  [RES_0402]  153.29 105.28 90 bottom
R525  1K  [RES_0402]  150.11 109.09 180 bottom
R526  2K  [RES_0402]  149.99 110.36 0 bottom
R527  0.01  [RES_0805]  146.81 109.09 0 bottom
R528  1K  [RES_0402]  54.48 105.66 180 bottom
R529  22K  [RES_0603]  21.34 110.36 180 bottom
R530  3.3K  [RES_0402]  18.16 108.2 270 bottom
R531  1.5K  [RES_0603]  17.4 110.49 180 bottom
R532  0  [RES_0402]  191.9 103.12 90 bottom
R533  0  [RES_0402]  191.01 103.12 90 bottom
R534  10K  [RES_0402]  189.1 103.12 270 bottom
R535  10K  [RES_0402]  188.21 103.12 90 bottom
R536  0.36  [402]  100.76 98.22 180 bottom
R537  33  [RES_0402]  80.07 103.44 90 bottom
R538  33  [RES_0402]  79.06 103.5 90 bottom
R539  33  [RES_0402]  77.53 103.5 90 bottom
R540  33  [RES_0402]  76.52 103.5 90 bottom
R541  33  [RES_0402]  75.63 103.5 270 bottom
R542  33  [RES_0402]  74.61 103.5 270 bottom
R543  33  [RES_0402]  73.6 103.5 90 bottom
R544  33  [RES_0402]  72.07 103.5 90 bottom
R545  33  [RES_0402]  71.06 103.5 90 bottom
R546  33  [RES_0402]  70.04 103.5 270 bottom
R547  33  [RES_0402]  68.67 103.47 270 bottom
R548  1K  [RES_0402]  66.61 100.58 270 bottom
R549  1K  [RES_0402]  65.72 100.58 270 bottom
R550  10K  [RES_0402]  185.42 95.89 0 bottom
R551  0.01  [RES_0805]  149.48 94.49 180 bottom
R552  0  [RES_0402]  110.11 90.42 0 bottom
R553  0  [RES_0402]  110.11 89.66 0 bottom
R554  1K  [RES_0402]  107.95 96.14 270 bottom
R555  100  [RES_0402]  92.46 90.81 180 bottom
R556  1M  [RES_0402]  91.44 91.82 0 bottom
R557  0  [RES_0402]  90.42 94.49 0 bottom
R558  1.00  [402]  82.19 95.4 0 bottom
R559  1K  [RES_0402]  79.19 96.4 180 bottom
R560  33  [RES_0402]  75.31 90.55 0 bottom
R561  0  [RES_0402]  75.31 89.66 180 bottom
R562  10K  [RES_0402]  73.53 90.55 0 bottom
R563  150  [RES_1206]  152.15 84.58 180 bottom
R564  33  [RES_0402]  76.33 87.88 0 bottom
R565  33  [RES_0402]  76.33 85.09 0 bottom
R566  0  [RES_0402]  75.37 84.01 180 bottom
R567  0  [RES_0402]  75.37 83.06 180 bottom
R568  0  [RES_0402]  75.31 88.77 180 bottom
R569  0  [RES_0402]  75.25 86.93 180 bottom
R570  0  [RES_0402]  75.25 85.98 180 bottom
R571  10K  [RES_0402]  74.42 85.09 0 bottom
R572  10K  [RES_0402]  73.91 87.88 0 bottom
R573  10K  [RES_0402]  51.79 87.07 0 bottom
R574  10K  [RES_0402]  185.67 79.63 270 bottom
R575  10K  [RES_0402]  184.4 80.9 270 bottom
R576  150  [RES_1206]  167.77 80.77 90 bottom
R577  150  [RES_1206]  165.48 80.77 90 bottom
R578  33  [RES_0402]  158.49 77.85 180 bottom
R579  33  [RES_0402]  99.2 76.02 180 bottom
R580  0  [RES_0402]  75.37 82.11 180 bottom
R581  0  [RES_0402]  75.37 81.15 180 bottom
R582  0  [RES_0402]  75.37 80.2 180 bottom
R583  0  [RES_0402]  75.37 79.25 180 bottom
R584  0  [RES_0402]  61.72 78.23 90 bottom
R585  22  [RES_0402]  60.45 78.23 90 bottom
R586  10K  [RES_0402]  50.04 78.23 90 bottom
R587  0  [RES_0402]  191.01 73.91 180 bottom
R588  0  [RES_0402]  191.01 73.03 180 bottom
R589  0  [RES_0402]  191.01 72.14 180 bottom
R590  0  [RES_0402]  191.01 69.47 180 bottom
R591  0  [RES_0402]  179.2 74.04 0 bottom
R592  0  [RES_0402]  179.2 73.15 0 bottom
R593  0  [RES_0402]  179.2 70.74 0 bottom
R594  0.01  [RES_0805]  154.18 69.72 0 bottom
R595  10  [RES_0402]  112.97 69.22 0 bottom
R596  33  [RES_0402]  111.82 73.79 180 bottom
R597  33  [RES_0402]  111.82 72.9 180 bottom
R598  33  [RES_0402]  111.82 71.88 180 bottom
R599  33  [RES_0402]  111.82 70.99 180 bottom
R600  4.7K  [RES_0402]  109.54 69.34 180 bottom
R601  1K  [RES_0402]  78.23 72.77 0 bottom
R602  22  [RES_0402]  44.2 72.39 180 bottom
R603  10K  [RES_0402]  24.77 72.77 180 bottom
R604  10K  [RES_0402]  24.38 75.18 270 bottom
R605  3.3K  [RES_0402]  19.94 72.64 0 bottom
R606  47K  [RES_0402]  183.01 68.33 90 bottom
R607  0  [RES_0402]  181.74 68.33 270 bottom
R608  330  [RES_0402]  180.47 68.33 90 bottom
R609  0  [RES_0805]  168.02 64.9 0 bottom
R610  2K  [RES_0402]  155.45 60.96 270 bottom
R611  0.1  [RES_0805]  149.1 64.01 180 bottom
R612  0  [RES_0402]  146.11 64.26 0 bottom
R613  0  [RES_0402]  137.6 66.29 180 bottom
R614  0  [RES_0402]  133.54 62.26 180 bottom
R615  0  [RES_0402]  133.54 61.24 180 bottom
R616  18K  [RES_0402]  133.29 65.43 180 bottom
R617  14.3K  [RES_0402]  133.29 64.54 0 bottom
R618  0  [RES_0402]  124.46 65.66 270 bottom
R619  33  [RES_0402]  123.95 68.15 180 bottom
R620  0  [RES_0402]  123.44 65.66 270 bottom
R621  0  [RES_0402]  121.56 67.39 0 bottom
R622  0  [RES_0402]  121.41 65.66 270 bottom
R623  0  [RES_0402]  119.25 66.78 270 bottom
R624  33  [RES_0402]  118.87 64.44 270 bottom
R625  0  [RES_0402]  117.27 63.12 180 bottom
R626  10  [RES_0402]  112.97 67.69 0 bottom
R627  10  [RES_0402]  112.97 66.8 0 bottom
R628  10  [RES_0402]  112.97 64.52 0 bottom
R629  10  [RES_0402]  112.97 62.99 0 bottom
R630  10  [RES_0402]  112.97 62.23 0 bottom
R631  33  [RES_0402]  109.54 68.33 180 bottom
R632  0  [RES_0402]  109.54 67.31 180 bottom
R633  10  [RES_0402]  109.54 65.28 0 bottom
R634  10  [RES_0402]  109.54 64.52 0 bottom
R635  10  [RES_0402]  109.54 62.99 0 bottom
R636  10  [RES_0402]  109.54 60.71 0 bottom
R637  1K  [RES_0402]  66.99 67.44 0 bottom
R638  1K  [RES_0402]  66.99 66.55 0 bottom
R639  1K  [RES_0402]  66.99 65.66 0 bottom
R640  1K  [RES_0402]  66.99 64.77 0 bottom
R641  1K  [RES_0402]  66.99 63.88 0 bottom
R642  22  [RES_0402]  44.07 63.5 180 bottom
R643  22  [RES_0402]  32.13 63.75 180 bottom
R644  22  [RES_0402]  32.13 62.74 180 bottom
R645  22  [RES_0402]  32.13 61.72 180 bottom
R646  3.3K  [RES_0402]  24.4 67.95 0 bottom
R647  3.3K  [RES_0402]  172.28 59.75 180 bottom
R648  33  [RES_0402]  170.05 57.53 180 bottom
R649  3.3K  [RES_0402]  169.74 55.31 270 bottom
R650  33  [RES_0402]  167.13 56.39 90 bottom
R651  1.6K  [RES_0402]  155.45 59.06 270 bottom
R652  1.6K  [RES_0402]  152.91 52.58 270 bottom
R653  0  [RES_0402]  152.27 59.56 0 bottom
R654  3.3K  [RES_0402]  152.27 58.67 0 bottom
R655  0  [RES_0402]  152.27 57.66 0 bottom
R656  3.3K  [RES_0402]  152.27 56.64 0 bottom
R657  0  [RES_0402]  152.27 55.75 0 bottom
R658  3.3K  [RES_0402]  152.27 54.74 0 bottom
R659  2K  [RES_0402]  152.02 52.58 90 bottom
R660  787  [RES_0402]  149.07 56.34 180 bottom
R661  1.8K  [RES_0402]  148.72 57.66 0 bottom
R662  18K  [RES_0402]  146.37 56.77 0 bottom
R663  14.3K  [RES_0402]  146.37 55.88 180 bottom
R664  3K  [RES_0402]  133.54 59.56 180 bottom
R665  10K  [RES_0402]  133.54 58.67 0 bottom
R666  0  [RES_0402]  133.41 56.39 180 bottom
R667  0  [RES_0402]  133.41 55.5 180 bottom
R668  4.02K  [RES_0603]  122.43 58.17 90 bottom
R669  0  [RES_0402]  120.78 52.6 90 bottom
R670  1K  [RES_0402]  120.4 58.55 270 bottom
R671  0  [RES_0402]  118.01 59.74 270 bottom
R672  3.3K  [RES_0402]  116.69 59.03 270 bottom
R673  10  [RES_0402]  112.97 59.94 0 bottom
R674  33  [RES_0402]  109.54 59.94 180 bottom
R675  3.3K  [RES_0402]  109.54 59.18 0 bottom
R676  3.3K  [RES_0402]  109.54 58.29 0 bottom
R677  33  [RES_0402]  109.54 57.4 180 bottom
R678  33  [RES_0402]  109.54 56.52 180 bottom
R679  33  [RES_0402]  106.49 59.31 90 bottom
R680  33  [RES_0402]  104.17 59.69 90 bottom
R681  10K  [RES_0402]  61.47 58.8 90 bottom
R682  0  [RES_0402]  58.14 55.66 270 bottom
R683  0  [RES_0402]  57.18 55.66 270 bottom
R684  10K  [RES_0402]  56.17 55.66 90 bottom
R685  0  [RES_0402]  55.09 55.66 270 bottom
R686  0  [RES_0402]  54.07 55.66 90 bottom
R687  0  [RES_0402]  53.06 55.66 90 bottom
R688  10K  [RES_0402]  53.06 53.06 270 bottom
R689  0  [RES_0402]  52.04 55.66 90 bottom
R690  10K  [RES_0402]  49.13 58.33 270 bottom
R691  3.3K  [RES_0402]  170.81 45.72 90 bottom
R692  10K  [RES_0402]  167.96 48.26 270 bottom
R693  3.3K  [RES_0402]  125.48 51.18 180 bottom
R694  0  [RES_0402]  124.08 48.64 0 bottom
R695  10K  [RES_0402]  121.54 48.64 0 bottom
R696  10K  [RES_0402]  46.67 47.31 270 bottom
R697  10K  [RES_0402]  39.37 44.45 0 bottom
R698  0.01  [RES_0805]  192.84 38.81 90 bottom
R699  3.3K  [RES_0402]  178.41 38.67 0 bottom
R700  3.3K  [RES_0402]  174.37 38.69 0 bottom
R701  1K  [RES_0402]  171.92 38.61 180 bottom
R702  0.01  [RES_0805]  148.21 41.78 180 bottom
R703  110  [RES_0805]  133.86 37.59 180 bottom
R704  10K  [RES_0402]  131.32 39.37 0 bottom
R705  100K  [RES_0402]  128.91 42.29 90 bottom
R706  2.2K  [RES_0603]  128.02 40.64 180 bottom
R707  33  [RES_0402]  45.4 36.83 0 bottom
R708  10K  [RES_0402]  39.37 41.91 0 bottom
R709  10K  [RES_0402]  39.37 39.37 0 bottom
R710  10K  [RES_0402]  39.37 36.83 0 bottom
R711  2K  [RES_0402]  172.09 29.21 0 bottom
R712  3.3K  [RES_0402]  126.7 30.43 0 bottom
R713  1K  [RES_0402]  124.46 32.39 90 bottom
R714  1K  [RES_0402]  124.38 30.1 270 bottom
R715  10K  [RES_0402]  39.37 34.29 0 bottom
R716  10K  [RES_0402]  39.37 31.75 0 bottom
R717  1K  [RES_0402]  39.37 29.21 0 bottom
R718  68  [RES_1210]  167.77 21.44 0 bottom
R719  68  [RES_1210]  155.7 21.44 0 bottom
R720  68  [RES_1210]  142.37 21.44 0 bottom
R721  10K  [RES_0402]  57.78 22.23 270 bottom
R722  0  [RES_0402]  56.52 26.04 0 bottom
R723  1K  [RES_0402]  46.67 26.99 0 bottom
R724  10K  [RES_0402]  39.05 25.08 0 bottom
R725  220  [RES_0603]  193.88 14.63 180 bottom
R726  33  [RES_0402]  193.52 19.58 180 bottom
R727  1K  [RES_0402]  193.01 16.51 180 bottom
R728  1K  [RES_0402]  192.99 18.31 180 bottom
R729  1K  [RES_0402]  192.99 17.27 180 bottom
R730  1K  [RES_0402]  191.13 14.61 180 bottom
R731  1K  [RES_0402]  190.63 13.33 180 bottom
R732  2.4  [RES_1210]  163.45 19.43 270 bottom
R733  2.4  [RES_1210]  151.38 19.43 270 bottom
R734  2.4  [RES_1210]  138.05 19.43 270 bottom
R735  1K  [RES_0402]  132.91 19.81 90 bottom
R736  100  [RES_0402]  61.8 16.66 0 bottom
R737  1K  [RES_0402]  60.96 19.05 0 bottom
R738  33  [RES_0402]  41.91 16.51 180 bottom
R739  33  [RES_0402]  41.91 15.24 180 bottom
R740  1K  [RES_0402]  16.26 14.35 180 bottom
R741  220  [RES_0603]  193.72 12.12 180 bottom
R742  220  [RES_0603]  193.72 10.79 180 bottom
R743  1K  [RES_0402]  190.94 12.07 180 bottom
R744  10K  [RES_0402]  187.01 11.43 0 bottom
R745  10K  [RES_0402]  183.51 13.02 270 bottom
R746  10K  [RES_0402]  176.15 8.51 0 bottom
R747  68  [RES_1210]  167.77 7.47 0 bottom
R748  68  [RES_1210]  155.7 7.47 0 bottom
R749  68  [RES_1210]  143.64 7.47 0 bottom
R750  2.2K  [RES_0603]  108.59 33.27 0 bottom
R751  100K  [RES_0402]  108.08 31.88 0 bottom
R752  10K  [RES_0402]  106.43 32.26 90 bottom
R753  100K  [RES_0402]  104.78 32.26 270 bottom
R754  10K  [RES_0402]  103.76 32.26 90 bottom
R755  2.2K  [RES_0603]  102.49 32.89 90 bottom
R756  75  [RES_0603]  67.69 30.73 180 bottom
R757  1K  [RES_0402]  67.18 24.51 0 bottom
R758  33  [RES_0402]  51.79 10.54 0 bottom
R759  33  [RES_0402]  47.6 12.3 270 bottom
R760  1K  [RES_0402]  43.81 6.1 270 bottom
R761  33  [RES_0402]  44.42 12.81 270 bottom
R762  1K  [RES_0402]  42.55 6.1 270 bottom
R763  10K  [RES_0402]  22.61 8 270 bottom
R764  1K  [RES_0402]  21.46 8 90 bottom
R765  0  [RES_0402]  9.65 7.11 0 bottom
R766  0  [RES_0402]  9.65 6.1 0 bottom
R767  10K  [RES_0402]  172.34 3.43 0 bottom
R768  2.4  [RES_1210]  163.45 5.46 270 bottom
R769  2.4  [RES_1210]  151.38 5.46 270 bottom
R770  2.4  [RES_1210]  139.32 5.46 270 bottom
R771  110  [RES_0805]  112.78 25.65 90 bottom
R772  110  [RES_0805]  101.73 22.99 0 bottom
R773  75  [RES_0603]  71.12 42.04 270 bottom
R774  6.49K  [RES_0402]  19.81 3.81 90 bottom
R775  10K  [RES_0402]  18.41 3.81 90 bottom
R776  0  [RES_0402]  15.88 3.3 270 bottom
R777  0  [RES_0402]  14.99 3.3 270 bottom
R778  0  [RES_0402]  13.34 3.3 90 bottom
RN500  10K  [RNET8-EXB38V_PAN]  53.02 109.86 0 bottom
RN501  10K  [RNET8-EXB38V_PAN]  56.83 92.08 180 bottom
RN502  10K  [RNET8-EXB38V_PAN]  56.83 87.95 180 bottom
RN503  10K  [RNET8-EXB38V_PAN]  50.16 83.82 0 bottom
RN504  33  [RNET16-EXB-2HV_PAN]  74.87 70.61 180 bottom
RN505  33  [RNET16-EXB-2HV_PAN]  74.87 66.17 180 bottom
SW1  SW SPST  [SW_GT12]  60.71 12.57 0 top
TP1  Testpoint  [TP]  133.67 118.75 0 top
TP2  Testpoint  [TP]  134.3 114.3 0 top
TP3  Testpoint  [TP]  167.79 112.63 270 top
TP4  Testpoint  [TP]  46.04 110.49 0 top
TP5  Testpoint  [TP]  84.45 109.86 0 top
TP6  Testpoint  [TP]  105.09 106.68 0 top
TP7  Testpoint  [TP]  106.87 103.12 0 top
TP8  Testpoint  [TP]  108.65 105.41 0 top
TP9  Testpoint  [TP]  110.3 103.12 0 top
TP10  Testpoint  [TP]  111.57 105.16 0 top
TP11  Testpoint  [TP]  114.1 103.58 0 top
TP12  Testpoint  [TP]  118.2 106.4 0 top
TP13  Testpoint  [TP]  118.25 104.11 0 top
TP14  Testpoint  [TP]  134.8 105.74 270 top
TP15  Testpoint  [TP]  162.35 101.73 0 top
TP16  Testpoint  [TP]  141.22 98.04 270 top
TP17  Testpoint  [TP]  145.03 96.9 270 top
TP18  Testpoint  [TP]  128.4 92.84 0 top
TP19  Testpoint  [TP]  135.64 90.22 0 top
TP20  Testpoint  [TP]  191.01 88.52 0 top
TP21  Testpoint  [TP]  127.95 79.38 0 top
TP22  Testpoint  [TP]  156.21 85.72 270 top
TP23  Testpoint  [TP]  187.96 84.46 0 top
TP24  Testpoint  [TP]  129.86 74.3 0 top
TP25  Testpoint  [TP]  143.13 75.18 270 top
TP26  Testpoint  [TP]  16.19 63.82 0 top
TP27  Testpoint  [TP]  17.78 61.59 0 top
TP28  Testpoint  [TP]  19.37 63.82 0 top
TP29  Testpoint  [TP]  20.95 61.59 0 top
TP30  Testpoint  [TP]  22.54 63.82 0 top
TP31  Testpoint  [TP]  23.49 61.59 0 top
TP32  Testpoint  [TP]  153.62 65.91 270 top
TP33  Testpoint  [TP]  166.17 61.49 270 top
TP34  Testpoint  [TP]  127.57 56.9 0 top
TP35  Testpoint  [TP]  135.45 54.93 270 top
TP36  Testpoint  [TP]  164.34 54.36 270 top
TP37  Testpoint  [TP]  109.28 43.94 0 top
TP38  Testpoint  [TP]  133.35 44.58 180 top
TP39  Testpoint  [TP]  139.95 45.34 270 top
TP40  Testpoint  [TP]  143.76 44.2 270 top
TP41  Testpoint  [TP]  171.32 52.45 270 top
TP42  Testpoint  [TP]  175.58 48.9 270 top
TP43  Testpoint  [TP]  178.18 49.53 0 top
TP44  Testpoint  [TP]  116.52 41.28 0 top
TP45  Testpoint  [TP]  190.37 40.26 0 top
TP46  Testpoint  [TP]  120.33 34.61 0 top
TP47  Testpoint  [TP]  120.65 31.75 0 top
TP48  Testpoint  [TP]  122.87 34.61 0 top
TP49  Testpoint  [TP]  131.57 32.3 0 top
TP50  Testpoint  [TP]  55.42 23.22 0 top
TP51  Testpoint  [TP]  39.57 12.04 0 top
TP52  Testpoint  [TP]  39.62 9.65 0 top
TP53  Testpoint  [TP]  55.24 10.03 0 top
TP54  Testpoint  [TP]  55.27 12.24 0 top
TP55  Testpoint  [TP]  28.19 11.3 0 top
TP56  Testpoint  [TP]  30.18 11.23 0 top
TP57  Testpoint  [TP]  32.14 11.25 0 top
TP58  Testpoint  [TP]  34.05 11.21 0 top
TP59  Testpoint  [TP]  99.57 28.58 0 top
TP60  Testpoint  [TP]  105.65 35.37 0 top
TP61  Testpoint  [TP]  107.56 35.37 0 top
TP62  Testpoint  [TP]  110.62 31.37 0 top
TP63  Testpoint  [TP]  14.48 8.76 0 top
TP64  Testpoint  [TP]  36.01 11.16 0 top
U1  IR_RECVR  [VISHAY_IR_TSOP348]  17.78 121.16 180 top
U2  PMD1000  [QF48_PPAD]  161.16 113.54 180 top
U3  TILT  [LCC8-MXD2125_MEMSIC]  182.63 115.06 180 top
U4  74CBTLV16212  [SOIC56-DGG_TI]  75.31 107.25 180 top
U5  TILT_I2C  [LCC8-MXD2125_MEMSIC]  182.63 107.44 180 top
U6  SN75C3232E  [SOIC16-PW_TI]  189.74 106.05 180 top
U7  TPS54327  [SOIC8-DDA_TI]  177.16 97.16 180 top
U8  74LVC827A  [SOIC24-PW_TI]  60.96 90.17 270 top
U9  74LVC2G126  [SSOP_8]  130.75 83.69 180 top
U10  74LVC2G126  [SSOP_8]  135.19 83.69 180 top
U11  DLPCA442xAHV  [BGA552-DDP4422_TI_MOD]  93.66 76.2 0 top
U12  SN75C3232E  [SOIC16-PW_TI]  190.12 73.53 180 top
U13  SRAM  [TSOPII_44]  38.1 67.95 90 top
U14  Flash  [TSOP_56_48_DUAL_SKT]  55.24 68.58 90 top
U15  PMD1000  [QF48_PPAD]  159.89 60.83 180 top
U16  AT24C32D  [TSSOP_8]  177.42 24.26 270 top
U17  LM317L  [SOIC8-D_TI]  184.09 28.49 270 top
U18  74LVC1G07  [SOT23-DBV_TI]  130.05 18.8 180 top
U19  74LVC1G126  [SOT23-DBV_TI]  165.73 17.78 0 top
U20  TMP100  [SOIC6-DBV_TI]  177.42 20.19 0 top
U21  TCA8418  [PQFP24-QFN-25_SI]  185.42 13.65 180 top
U22  IR_RECVR  [VISHAY_IR_TSOP348]  183.51 4.45 0 top
U500  74LVC1G126  [SOT23-DBV_TI]  17.78 124.97 180 bottom
U501  AD5252  [TSSOP_14]  174.94 117.22 0 bottom
U502  TPD4E1U06  [SOIC6-DBV_TI]  20.07 114.3 0 bottom
U503  74LVC1G125  [SOT23-DBV_TI]  20.45 107.44 0 bottom
U504  TPD4E001  [SOIC6-DRL_TI]  22.75 75.56 0 bottom
U505  Low Power Microcontroller  [SOIC14-PW_TI]  184.91 72.77 270 bottom
U506  TPD4E001  [SOIC6-DRL_TI]  22.75 70.8 0 bottom
U507  AD5252  [TSSOP_14]  141.16 62.99 90 bottom
U508  74LVC1G125  [SOT23-DBV_TI]  122.43 62.23 180 bottom
U509  AD5252  [TSSOP_14]  141.29 57.4 90 bottom
U510  74LVC1G07  [SOT23-DBV_TI]  43.18 44.77 90 bottom
U511  TPS3838  [SOT23-DBV_TI]  43.18 48.58 270 bottom
U512  LM393  [SOIC8-PW_TI]  133.86 41.66 90 bottom
U513  74AUP1G79  [SOIC5-DBV_TI]  51.84 24.51 180 bottom
U514  74AHC1G125  [SOT23-DBV_TI]  42.86 26.04 90 bottom
U515  74LVC827A  [SOIC24-PW_TI]  28.77 22.48 270 bottom
U516  74LVC541A  [SOIC20-DGV_TI]  48.84 16.13 270 bottom
U517  74LVC827A  [SOIC24-PW_TI]  7.11 14.48 90 bottom
U518  74LVC1G126  [SOT23-DBV_TI]  182.12 7.49 270 bottom
U519  LM393  [SOIC8-PW_TI]  104.65 29.46 270 bottom
U520  74LVC1G125  [SOT23-DBV_TI]  68.07 40.26 90 bottom
U521  74LVC1G125  [SOT23-DBV_TI]  67.69 27.43 180 bottom
U522  74LVC1G17  [SOT23-DBV_TI]  17.14 8 180 bottom
U523  74LVC1G06  [SOIC5-DBV_TI]  15.49 12.19 0 bottom
U524  74LVC1G125  [SOT23-DBV_TI]  12.32 6.6 0 bottom
VR1  20K  [POT-3314G]  95.88 30.99 90 top
VR2  20K  [POT-3314G]  115.44 31.37 270 top
X500  20.0 MHz  [SMD_49]  91.82 100.84 0 bottom

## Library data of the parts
C1 C15 C20 C22 C23 C26 C31 C36 C522 C524 C552 C641 C643 C647 C656-C658 C667-C669 = CAP NP: Tolerance: TOL
C2-C14 C16-C19 C21 C24 C25 C27-C30 C32-C35 C37-C42 C500-C521 C523 C525-C546 C548-C551 C553-C605 C607-C630 C632-C638 C640 C642 C644-C646 C648-C655 C659-C666 C670-C676 = CAP NP
C547 C606 C631 C639 = CAP POL
D1-D4 D6-D8 D501-D507 = DIODE_SCHOTTKY
D5 D500 = DIODE
D9-D15 = LED_0
DN500-DN503 DN505-DN508 = DS_DUAL_S_AJK
DN504 = DS_DUAL_CK_JAA_0
FB1 = FERRITE
FB2 FB3 FB500-FB506 L1-L9 L500-L505 = INDUCTOR
J1 J2 = conn_120_QTH
J3 J9-J13 J21 J29 J40 J41 J44 J46 = JUMPER-1x3
J4 J56 J58 = CON4
J5 J6 J8 J20 J31 J34 J45 = HDR_2
J7 J16 = RS232
J14 J15 = CONN10
J17 J24 = CON5
J18 = CON22
J19 J23 = CON20A
J22 = POWER_12V_INPUT
J25 J26 J30 J37-J39 J52 J53 J55 J57 J59-J62 = CON3
J27 = ARM_TRACE_PORT
J28 J33 = CON12
J32 = JUMPER_8A
J35 J47 = CON14
J36 J49-J51 = CONN_4
J42 J43 J48 = CON6
J54 = 12 HEADER
J63 = FMC 400POS CONNECTOR
MT1-MT6 = Testpoint_0
Q1 Q2 Q500 Q505 = NTD14NO3RT4
Q3 Q4 Q501-Q504 Q507 = 2N2222A
Q5 = NTF6P02T3G
Q506 = FDN306P_1
R1-R74 R500-R717 R721-R731 R735-R746 R750-R767 R771-R778 = R
R718-R720 R732-R734 R747-R749 R768-R770 = R: Tolerance: TOL
RN500-RN503 = RPACK_4
RN504 RN505 = RESISTOR DIP 8
SW1 = SW SPST_1
TP1-TP64 = Testpoint
U1 U22 = IR_RECVR
U2 U15 = PMD1000
U3 = TILT
U4 = SN74CBTLV16212
U5 = TILT_I2C
U6 U12 = MAX3232
U7 = TPS54327
U8 U517 = SN74LVC827A
U9 U10 = SN74LVC2G126
U11 = DDP442x
U13 = SRAM_ALLIANCE
U14 = FLASH_SPANSION
U16 = EEPROM
U17 = LM317L
U18 U510 = 74LVC1G07
U19 U500 U518 = 74LVC1G126
U20 = TEMP
U21 = TCA8418_0
U501 U507 U509 = AD525X
U502 = TPD4E1U06
U503 U508 U520 U521 U524 = 74LVC1G125
U504 U506 = TPD4E001
U505 = MSP430
U511 = TPS3838
U512 U519 = OPAMP_DUAL
U513 = 74AUP1G79
U514 = 74AHC1G125
U515 = 74LVC827A
U516 = SN74LVC541ADGVR
U522 = 74LVC1G17
U523 = SN74LVC1G06
VR1 VR2 = POT_R_S
X500 = CRYSTAL

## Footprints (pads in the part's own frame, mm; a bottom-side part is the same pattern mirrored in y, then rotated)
402
  rect 0.813x0.711 smd: 1(-0.648,0) 2(0.648,0)
BGA552-DDP4422_TI_MOD
  round 0.559 smd: A1(-12.5,-12.5) A2(-12.5,-11.5) A3(-12.5,-10.5) A4(-12.5,-9.5) A5(-12.5,-8.5) A6(-12.5,-7.5) A7(-12.5,-6.5) A8(-12.5,-5.5) A9(-12.5,-4.5) A10(-12.5,-3.5) A11(-12.5,-2.5) A12(-12.5,-1.5) A13(-12.5,-0.5) A14(-12.5,0.5) A15(-12.5,1.5) A16(-12.5,2.5) A17(-12.5,3.5) A18(-12.5,4.5) A19(-12.5,5.5) A20(-12.5,6.5) A21(-12.5,7.5) A22(-12.5,8.5) A23(-12.5,9.5) A24(-12.5,10.5) A25(-12.5,11.5) A26(-12.5,12.5) AA1(7.5,-12.5) AA2(7.5,-11.5) AA3(7.5,-10.5) AA4(7.5,-9.5) AA5(7.5,-8.5) AA6(7.5,-7.5) AA7(7.5,-6.5) AA8(7.5,-5.5) AA9(7.5,-4.5) AA10(7.5,-3.5) AA11(7.5,-2.5) AA12(7.5,-1.5) AA13(7.5,-0.5) AA14(7.5,0.5) AA15(7.5,1.5) AA16(7.5,2.5) AA17(7.5,3.5) AA18(7.5,4.5) AA19(7.5,5.5) AA20(7.5,6.5) AA21(7.5,7.5) AA22(7.5,8.5) AA23(7.5,9.5) AA24(7.5,10.5) AA25(7.5,11.5) AA26(7.5,12.5) AB1(8.5,-12.5) AB2(8.5,-11.5) AB3(8.5,-10.5) AB4(8.5,-9.5) AB5(8.5,-8.5) AB6(8.5,-7.5) AB7(8.5,-6.5) AB8(8.5,-5.5) AB9(8.5,-4.5) AB10(8.5,-3.5) AB11(8.5,-2.5) AB12(8.5,-1.5) AB13(8.5,-0.5) AB14(8.5,0.5) AB15(8.5,1.5) AB16(8.5,2.5) AB17(8.5,3.5) AB18(8.5,4.5) AB19(8.5,5.5) AB20(8.5,6.5) AB21(8.5,7.5) AB22(8.5,8.5) AB23(8.5,9.5) AB24(8.5,10.5) AB25(8.5,11.5) AB26(8.5,12.5) AC1(9.5,-12.5) AC2(9.5,-11.5) AC3(9.5,-10.5) AC4(9.5,-9.5) AC5(9.5,-8.5) AC6(9.5,-7.5) AC7(9.5,-6.5) AC8(9.5,-5.5) AC9(9.5,-4.5) AC10(9.5,-3.5) AC11(9.5,-2.5) AC12(9.5,-1.5) AC13(9.5,-0.5) AC14(9.5,0.5) AC15(9.5,1.5) AC16(9.5,2.5) AC17(9.5,3.5) AC18(9.5,4.5) AC19(9.5,5.5) AC20(9.5,6.5) AC21(9.5,7.5) AC22(9.5,8.5) AC23(9.5,9.5) AC24(9.5,10.5) AC25(9.5,11.5) AC26(9.5,12.5) AD1(10.5,-12.5) AD2(10.5,-11.5) AD3(10.5,-10.5) AD4(10.5,-9.5) AD5(10.5,-8.5) AD6(10.5,-7.5) AD7(10.5,-6.5) AD8(10.5,-5.5) AD9(10.5,-4.5) AD10(10.5,-3.5) AD11(10.5,-2.5) AD12(10.5,-1.5) AD13(10.5,-0.5) AD14(10.5,0.5) AD15(10.5,1.5) AD16(10.5,2.5) AD17(10.5,3.5) AD18(10.5,4.5) AD19(10.5,5.5) AD20(10.5,6.5) AD21(10.5,7.5) AD22(10.5,8.5) AD23(10.5,9.5) AD24(10.5,10.5) AD25(10.5,11.5) AD26(10.5,12.5) AE1(11.5,-12.5) AE2(11.5,-11.5) AE3(11.5,-10.5) AE4(11.5,-9.5) AE5(11.5,-8.5) AE6(11.5,-7.5) AE7(11.5,-6.5) AE8(11.5,-5.5) AE9(11.5,-4.5) AE10(11.5,-3.5) AE11(11.5,-2.5) AE12(11.5,-1.5) AE13(11.5,-0.5) AE14(11.5,0.5) AE15(11.5,1.5) AE16(11.5,2.5) AE17(11.5,3.5) AE18(11.5,4.5) AE19(11.5,5.5) AE20(11.5,6.5) AE21(11.5,7.5) AE22(11.5,8.5) AE23(11.5,9.5) AE24(11.5,10.5) AE25(11.5,11.5) AE26(11.5,12.5) AF1(12.5,-12.5) AF2(12.5,-11.5) AF3(12.5,-10.5) AF4(12.5,-9.5) AF5(12.5,-8.5) AF6(12.5,-7.5) AF7(12.5,-6.5) AF8(12.5,-5.5) AF9(12.5,-4.5) AF10(12.5,-3.5) AF11(12.5,-2.5) AF12(12.5,-1.5) AF13(12.5,-0.5) AF14(12.5,0.5) AF15(12.5,1.5) AF16(12.5,2.5) AF17(12.5,3.5) AF18(12.5,4.5) AF19(12.5,5.5) AF20(12.5,6.5) AF21(12.5,7.5) AF22(12.5,8.5) AF23(12.5,9.5) AF24(12.5,10.5) AF25(12.5,11.5) AF26(12.5,12.5) B1(-11.5,-12.5) B2(-11.5,-11.5) B3(-11.5,-10.5) B4(-11.5,-9.5) B5(-11.5,-8.5) B6(-11.5,-7.5) B7(-11.5,-6.5) B8(-11.5,-5.5) B9(-11.5,-4.5) B10(-11.5,-3.5) B11(-11.5,-2.5) B12(-11.5,-1.5) B13(-11.5,-0.5) B14(-11.5,0.5) B15(-11.5,1.5) B16(-11.5,2.5) B17(-11.5,3.5) B18(-11.5,4.5) B19(-11.5,5.5) B20(-11.5,6.5) B21(-11.5,7.5) B22(-11.5,8.5) B23(-11.5,9.5) B24(-11.5,10.5) B25(-11.5,11.5) B26(-11.5,12.5) C1(-10.5,-12.5) C2(-10.5,-11.5) C3(-10.5,-10.5) C4(-10.5,-9.5) C5(-10.5,-8.5) C6(-10.5,-7.5) C7(-10.5,-6.5) C8(-10.5,-5.5) C9(-10.5,-4.5) C10(-10.5,-3.5) C11(-10.5,-2.5) C12(-10.5,-1.5) C13(-10.5,-0.5) C14(-10.5,0.5) C15(-10.5,1.5) C16(-10.5,2.5) C17(-10.5,3.5) C18(-10.5,4.5) C19(-10.5,5.5) C20(-10.5,6.5) C21(-10.5,7.5) C22(-10.5,8.5) C23(-10.5,9.5) C24(-10.5,10.5) C25(-10.5,11.5) C26(-10.5,12.5) D1(-9.5,-12.5) D2(-9.5,-11.5) D3(-9.5,-10.5) D4(-9.5,-9.5) D5(-9.5,-8.5) D6(-9.5,-7.5) D7(-9.5,-6.5) D8(-9.5,-5.5) D9(-9.5,-4.5) D10(-9.5,-3.5) D11(-9.5,-2.5) D12(-9.5,-1.5) D13(-9.5,-0.5) D14(-9.5,0.5) D15(-9.5,1.5) D16(-9.5,2.5) D17(-9.5,3.5) D18(-9.5,4.5) D19(-9.5,5.5) D20(-9.5,6.5) D21(-9.5,7.5) D22(-9.5,8.5) D23(-9.5,9.5) D24(-9.5,10.5) D25(-9.5,11.5) D26(-9.5,12.5) E1(-8.5,-12.5) E2(-8.5,-11.5) E3(-8.5,-10.5) E4(-8.5,-9.5) E5(-8.5,-8.5) E6(-8.5,-7.5) E7(-8.5,-6.5) E8(-8.5,-5.5) E9(-8.5,-4.5) E10(-8.5,-3.5) E11(-8.5,-2.5) E12(-8.5,-1.5) E13(-8.5,-0.5) E14(-8.5,0.5) E15(-8.5,1.5) E16(-8.5,2.5) E17(-8.5,3.5) E18(-8.5,4.5) E19(-8.5,5.5) E20(-8.5,6.5) E21(-8.5,7.5) E22(-8.5,8.5) E23(-8.5,9.5) E24(-8.5,10.5) E25(-8.5,11.5) E26(-8.5,12.5) F1(-7.5,-12.5) F2(-7.5,-11.5) F3(-7.5,-10.5) F4(-7.5,-9.5) F5(-7.5,-8.5) F6(-7.5,-7.5) F7(-7.5,-6.5) F8(-7.5,-5.5) F9(-7.5,-4.5) F10(-7.5,-3.5) F11(-7.5,-2.5) F12(-7.5,-1.5) F13(-7.5,-0.5) F14(-7.5,0.5) F15(-7.5,1.5) F16(-7.5,2.5) F17(-7.5,3.5) F18(-7.5,4.5) F19(-7.5,5.5) F20(-7.5,6.5) F21(-7.5,7.5) F22(-7.5,8.5) F23(-7.5,9.5) F24(-7.5,10.5) F25(-7.5,11.5) F26(-7.5,12.5) G1(-6.5,-12.5) G2(-6.5,-11.5) G3(-6.5,-10.5) G4(-6.5,-9.5) G5(-6.5,-8.5) G6(-6.5,-7.5) G21(-6.5,7.5) G22(-6.5,8.5) G23(-6.5,9.5) G24(-6.5,10.5) G25(-6.5,11.5) G26(-6.5,12.5) H1(-5.5,-12.5) H2(-5.5,-11.5) H3(-5.5,-10.5) H4(-5.5,-9.5) H5(-5.5,-8.5) H6(-5.5,-7.5) H21(-5.5,7.5) H22(-5.5,8.5) H23(-5.5,9.5) H24(-5.5,10.5) H25(-5.5,11.5) H26(-5.5,12.5) J1(-4.5,-12.5) J2(-4.5,-11.5) J3(-4.5,-10.5) J4(-4.5,-9.5) J5(-4.5,-8.5) J6(-4.5,-7.5) J21(-4.5,7.5) J22(-4.5,8.5) J23(-4.5,9.5) J24(-4.5,10.5) J25(-4.5,11.5) J26(-4.5,12.5) K1(-3.5,-12.5) K2(-3.5,-11.5) K3(-3.5,-10.5) K4(-3.5,-9.5) K5(-3.5,-8.5) K6(-3.5,-7.5) K21(-3.5,7.5) K22(-3.5,8.5) K23(-3.5,9.5) K24(-3.5,10.5) K25(-3.5,11.5) K26(-3.5,12.5) L1(-2.5,-12.5) L2(-2.5,-11.5) L3(-2.5,-10.5) L4(-2.5,-9.5) L5(-2.5,-8.5) L6(-2.5,-7.5) L11(-2.5,-2.5) L12(-2.5,-1.5) L13(-2.5,-0.5) L14(-2.5,0.5) L15(-2.5,1.5) L16(-2.5,2.5) L21(-2.5,7.5) L22(-2.5,8.5) L23(-2.5,9.5) L24(-2.5,10.5) L25(-2.5,11.5) L26(-2.5,12.5) M1(-1.5,-12.5) M2(-1.5,-11.5) M3(-1.5,-10.5) M4(-1.5,-9.5) M5(-1.5,-8.5) M6(-1.5,-7.5) M11(-1.5,-2.5) M12(-1.5,-1.5) M13(-1.5,-0.5) M14(-1.5,0.5) M15(-1.5,1.5) M16(-1.5,2.5) M21(-1.5,7.5) M22(-1.5,8.5) M23(-1.5,9.5) M24(-1.5,10.5) M25(-1.5,11.5) M26(-1.5,12.5) N1(-0.5,-12.5) N2(-0.5,-11.5) N3(-0.5,-10.5) N4(-0.5,-9.5) N5(-0.5,-8.5) N6(-0.5,-7.5) N11(-0.5,-2.5) N12(-0.5,-1.5) N13(-0.5,-0.5) N14(-0.5,0.5) N15(-0.5,1.5) N16(-0.5,2.5) N21(-0.5,7.5) N22(-0.5,8.5) N23(-0.5,9.5) N24(-0.5,10.5) N25(-0.5,11.5) N26(-0.5,12.5) P1(0.5,-12.5) P2(0.5,-11.5) P3(0.5,-10.5) P4(0.5,-9.5) P5(0.5,-8.5) P6(0.5,-7.5) P11(0.5,-2.5) P12(0.5,-1.5) P13(0.5,-0.5) P14(0.5,0.5) P15(0.5,1.5) P16(0.5,2.5) P21(0.5,7.5) P22(0.5,8.5) P23(0.5,9.5) P24(0.5,10.5) P25(0.5,11.5) P26(0.5,12.5) R1(1.5,-12.5) R2(1.5,-11.5) R3(1.5,-10.5) R4(1.5,-9.5) R5(1.5,-8.5) R6(1.5,-7.5) R11(1.5,-2.5) R12(1.5,-1.5) R13(1.5,-0.5) R14(1.5,0.5) R15(1.5,1.5) R16(1.5,2.5) R21(1.5,7.5) R22(1.5,8.5) R23(1.5,9.5) R24(1.5,10.5) R25(1.5,11.5) R26(1.5,12.5) T1(2.5,-12.5) T2(2.5,-11.5) T3(2.5,-10.5) T4(2.5,-9.5) T5(2.5,-8.5) T6(2.5,-7.5) T11(2.5,-2.5) T12(2.5,-1.5) T13(2.5,-0.5) T14(2.5,0.5) T15(2.5,1.5) T16(2.5,2.5) T21(2.5,7.5) T22(2.5,8.5) T23(2.5,9.5) T24(2.5,10.5) T25(2.5,11.5) T26(2.5,12.5) U1(3.5,-12.5) U2(3.5,-11.5) U3(3.5,-10.5) U4(3.5,-9.5) U5(3.5,-8.5) U6(3.5,-7.5) U21(3.5,7.5) U22(3.5,8.5) U23(3.5,9.5) U24(3.5,10.5) U25(3.5,11.5) U26(3.5,12.5) V1(4.5,-12.5) V2(4.5,-11.5) V3(4.5,-10.5) V4(4.5,-9.5) V5(4.5,-8.5) V6(4.5,-7.5) V21(4.5,7.5) V22(4.5,8.5) V23(4.5,9.5) V24(4.5,10.5) V25(4.5,11.5) V26(4.5,12.5) W1(5.5,-12.5) W2(5.5,-11.5) W3(5.5,-10.5) W4(5.5,-9.5) W5(5.5,-8.5) W6(5.5,-7.5) W21(5.5,7.5) W22(5.5,8.5) W23(5.5,9.5) W24(5.5,10.5) W25(5.5,11.5) W26(5.5,12.5) Y1(6.5,-12.5) Y2(6.5,-11.5) Y3(6.5,-10.5) Y4(6.5,-9.5) Y5(6.5,-8.5) Y6(6.5,-7.5) Y21(6.5,7.5) Y22(6.5,8.5) Y23(6.5,9.5) Y24(6.5,10.5) Y25(6.5,11.5) Y26(6.5,12.5)
